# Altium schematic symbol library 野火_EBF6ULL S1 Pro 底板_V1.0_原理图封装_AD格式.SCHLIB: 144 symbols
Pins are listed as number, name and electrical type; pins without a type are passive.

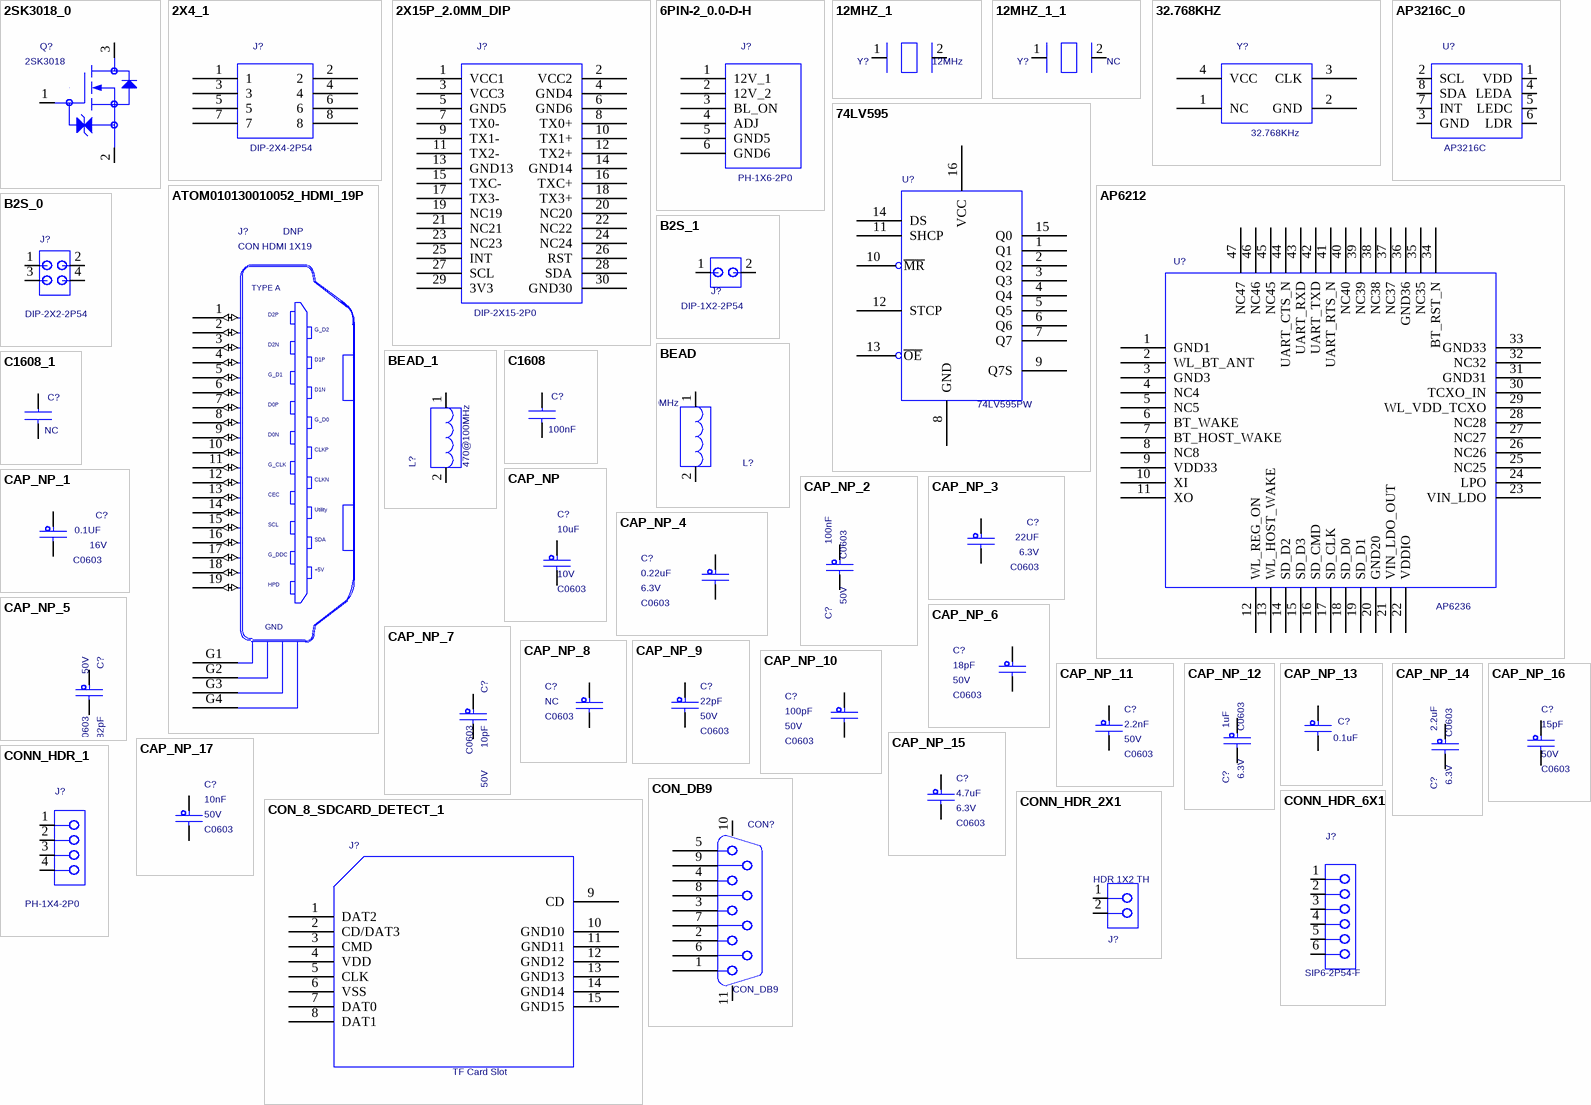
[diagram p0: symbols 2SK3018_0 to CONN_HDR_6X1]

## 2SK3018_0
designator Q?  value 2SK3018  (hidden comment: 2SK3018_0)
TRANS MOSFET N-CH 30V .1A SOT-323; PCB DECAL: SOT23; AGILE_PN: 480-75317; MFG_NAME01: ROHM; MFG_PN01: 2SK3018T106; CAD_APPROVED: Yes; Source_Path: H:\NXP_RT1050\SCH\CORE_SCH\IMXRT1052_180113.DSN; CLASS: IC
footprint SOT23
pins: 1 GATE, 2 SOURCE, 3 DRAIN

## 2X4_1
designator J?  value DIP-2X4-2P54  (hidden comment: 2X4_1)
Source_Path: D:\NXP_RT1050\RT1050_MB_PRO\SCH\IMXRT1052_MB_PRO_0321.DSN
footprint DIP-2X4-2P54
pins: 1, 2, 3, 4, 5, 6, 7, 8

## 2X15P_2.0MM_DIP
designator J?  value DIP-2X15-2P0  (hidden comment: 2X15P_2.0MM_DIP)
Source_Path: H:\NXP_RT1050\SCH\SCHLIB\YHSCHLIB.OLB
footprint DIP-2X15-2P0
pins: 1 VCC1, 2 VCC2, 3 VCC3, 4 GND4, 5 GND5, 6 GND6, 7 TX0-, 8 TX0+, 9 TX1-, 10 TX1+, 11 TX2-, 12 TX2+, 13 GND13, 14 GND14, 15 TXC-, 16 TXC+, 17 TX3-, 18 TX3+, 19 NC19, 20 NC20, 21 NC21, 22 NC22, 23 NC23, 24 NC24, 25 INT, 26 RST, 27 SCL, 28 SDA, 29 3V3, 30 GND30

## 6PIN-2_0.0-D-H
designator J?  value PH-1X6-2P0  (hidden comment: 6PIN-2_0.0-D-H)
Source_Path: H:\NXP_RT1050\SCH\IMXRT1052_MB.DSN
footprint PH-1X6-2P0
pins: 1 12V_1, 2 12V_2, 3 BL_ON, 4 ADJ, 5 GND5, 6 GND6

## 12MHZ_1
designator Y?  value 12MHz  (hidden comment: 12MHZ_1)
PCB DECAL: XTAL-DIP; Source_Path: H:\NXP_RT1050\SCH\IMXRT1052_MB.DSN
footprint XTAL-DIP
pins: 1, 2

## 12MHZ_1_1
designator Y?, comment value NC  (hidden comment: 12MHZ_1)
PCB DECAL: XTAL-DIP; Source_Path: H:\NXP_RT1050\SCH\IMXRT1052_MB.DSN
footprint XTAL-DIP
pins: 1, 2

## 32.768KHZ
designator Y?
PCB DECAL: 3225; Source_Path: F:\NXP\I.MX6UL\SCH\IMX6UL.OLB
footprint 3225
pins: 1 NC, 2 GND, 3 CLK, 4 VCC

## 74LV595
designator U?  value 74LV595PW  (hidden comment: 74LV595)
IC REG S 8BIT TS 1.0-3.6V TSSOP16; CAD_APPROVED: Yes; MFG_NAME01: PHILIPS SEMICONDUCTOR; AGILE_PN: 312-79843; Source_Path: Q:\ORCADCIS\SYMBOLS\FCL_IC5.OLB
footprint TSSOP16
pins: 1 Q1, 2 Q2, 3 Q3, 4 Q4, 5 Q5, 6 Q6, 7 Q7, 8 GND (power), 9 Q7S, 10 ~{MR}, 11 SHCP, 12 STCP, 13 ~{OE}, 14 DS, 15 Q0, 16 VCC (power)

## AP3216C_0
designator U?  value AP3216C  (hidden comment: AP3216C_0)
Source_Path: D:\NXP_RT1050\RT1050_MB_PRO\SCH\IMXRT1052_MB_PRO_0414.DSN
footprint AP3216C
pins: 1 VDD, 2 SCL, 3 GND, 4 LEDA, 5 LEDC, 6 LDR, 7 INT, 8 SDA

## AP6212
designator U?  value AP6236  (hidden comment: AP6212)
Source_Path: F:\NXP\I.MX6UL\SCH\IMX6UL.OLB
footprint AP6212
pins: 1 GND1, 2 WL_BT_ANT, 3 GND3, 4 NC4, 5 NC5, 6 BT_WAKE, 7 BT_HOST_WAKE, 8 NC8, 9 VDD33, 10 XI, 11 XO, 12 WL_REG_ON, 13 WL_HOST_WAKE, 14 SD_D2, 15 SD_D3, 16 SD_CMD, 17 SD_CLK, 18 SD_D0, 19 SD_D1, 20 GND20, 21 VIN_LDO_OUT, 22 VDDIO, 23 VIN_LDO, 24 LPO, 25 NC25, 26 NC26, 27 NC27, 28 NC28, 29 WL_VDD_TCXO, 30 TCXO_IN, 31 GND31, 32 NC32, 33 GND33, 34 BT_RST_N, 35 NC35, 36 GND36, 37 NC37, 38 NC38, 39 NC39, 40 NC40, 41 UART_RTS_N, 42 UART_TXD, 43 UART_RXD, 44 UART_CTS_N, 45 NC45, 46 NC46, 47 NC47

## ATOM010130010052_HDMI_19P
designator J?  value CON HDMI 1X19  ASSY_OPT: DNP  (hidden comment: ATOM010130010052_HDMI_19P)
CON 1X19 HDMI SMT 0.5MM 249H AU --; CAD_APPROVED: Yes; MFG_PN01: HD119F-3A04202; MFG_NAME01: SHENZHEN ATOM TECHNOLOGY CO.,LTD; AGILE_PN: 211-79674; PCB DECAL: CON_RA_HDMI_19P_0P5_SM; Source_Path: Q:\ORCADCIS\SYMBOLS\FCL_CONNECTOR.OLB; VPN: 1166-2C105-211; Vendor: Comtek; OriginalSymbolOrigin: (-200,650); CLASS: IO
footprint CON_RA_HDMI_19P_0P5_SM
pins: 1 D2+ (io), 2 D2GND (io), 3 D2- (io), 4 D1+ (io), 5 D1GND (io), 6 D1- (io), 7 D0+ (io), 8 D0GND (io), 9 D0- (io), 10 CK+ (io), 11 CKGND (io), 12 CK- (io), 13 CEC (io), 14 UTILITY (io), 15 SCL (io), 16 SDA (io), 17 DDCGND (io), 18 +5V (io), 19 HPD (io), G1 GND1 (power), G2 GND2 (power), G3 GND3 (power), G4 GND4 (power)

## B2S_0
designator J?  value DIP-2X2-2P54  (hidden comment: B2S_0)
Source_Path: E:\20200901_FPGA_A7\DEV\VERSION7\EBF_XC7A35T B1 DEV BOARD_20201024001.DSN
footprint DIP-2X2-2P54
pins: 1, 2, 3, 4

## B2S_1
designator J?  value DIP-1X2-2P54  (hidden comment: B2S_1)
PCB DECAL: HDR102; Source_Path: F:\STM32\F429\SCH\V4\STM32F429_F767_H743_MB_1129.DSN
footprint HDR102
pins: 1, 2

## BEAD
designator L?  value 330@100MHz  (hidden comment: BEAD)
IND FER BEAD 330OHM@100MHZ 1.7A 0603; PART_TYPE: FERRITE\BEAD; TOL: 25%; CAD_APPROVED: Yes; MFG_PN01: MPZ1608S331A; MFG_NAME01: TDK; AGILE_PN: 180-78156; PCB DECAL: L0603; Source_Path: Q:\ORCADCIS\SYMBOLS\FCL_INDUCTOR.OLB; CLASS: DISCRETE
footprint L0603
pins: 1, 2

## BEAD_1
designator L?, comment value 470@100MHz  (hidden comment: BEAD)
IND FER BEAD 330OHM@100MHZ 1.7A 0603; PART_TYPE: FERRITE\BEAD; PCB DECAL: L0603; AGILE_PN: 180-78156; Tolerance: 25%; MFG_NAME01: TDK; MFG_PN01: MPZ1608S331A; CAD_APPROVED: Yes; Source_Path: Q:\ORCADCIS\SYMBOLS\FCL_INDUCTOR.OLB; CLASS: DISCRETE
footprint L0603
pins: 1, 2

## C1608
designator C?  value 100nF  (hidden comment: C1608)
PCB DECAL: C0603; Source_Path: D:\SOPGODS_VIEW_AP\MOBILE_AP_APPLICATION\LIBRARY\ORCAD\DEVICE.OLB
footprint C0603
pins: 1, 2

## C1608_1
designator C?, comment value NC  (hidden comment: C1608)
PCB DECAL: C0603; Source_Path: D:\SOPGODS_VIEW_AP\MOBILE_AP_APPLICATION\LIBRARY\ORCAD\DEVICE.OLB
footprint C0603
pins: 1, 2

## CAP_NP
designator C?  value 10uF  PCB DECAL: C0603  voltage_rating: 10V  (hidden comment: CAP_NP)
CAP CER 22UF 6.3V 20% X5R 0603; FPLIST: CC0603_OV,CC0603,0603_CC; CAD_APPROVED: Yes; MFG_PN01: CL10A226MQ8NRNE; MFG_NAME01: Samsung; AGILE_PN: 150-78467; Source_Path: Q:\ORCADCIS\SYMBOLS\FCL_CAPACITOR.OLB; CLASS: DISCRETE
footprint C0603
pins: 1, 2

## CAP_NP_1
designator C?, comment value 0.1UF  voltage_rating: 16V  PCB DECAL: C0603  (hidden comment: CAP_NP)
CAP CER 22UF 6.3V 20% X5R 0603; AGILE_PN: 150-78467; MFG_NAME01: Samsung; MFG_PN01: CL10A226MQ8NRNE; CAD_APPROVED: Yes; FPLIST: CC0603_OV,CC0603,0603_CC; Source_Path: Q:\ORCADCIS\SYMBOLS\FCL_CAPACITOR.OLB; CLASS: DISCRETE
footprint C0603
pins: 1, 2

## CAP_NP_2
designator C?, comment value 100nF  voltage_rating: 50V  PCB DECAL: C0603  (hidden comment: CAP_NP)
CAP CER 22UF 6.3V 20% X5R 0603; FPLIST: CC0603_OV,CC0603,0603_CC; CAD_APPROVED: Yes; MFG_PN01: CL10A226MQ8NRNE; MFG_NAME01: Samsung; AGILE_PN: 150-78467; Source_Path: Q:\ORCADCIS\SYMBOLS\FCL_CAPACITOR.OLB; CLASS: DISCRETE
footprint C0603
pins: 1, 2

## CAP_NP_3
designator C?, comment value 22UF  PCB DECAL: C0603  voltage_rating: 6.3V  (hidden comment: CAP_NP)
CAP CER 22UF 6.3V 20% X5R 0603; AGILE_PN: 150-78467; MFG_NAME01: Samsung; MFG_PN01: CL10A226MQ8NRNE; CAD_APPROVED: Yes; FPLIST: CC0603_OV,CC0603,0603_CC; Source_Path: Q:\ORCADCIS\SYMBOLS\FCL_CAPACITOR.OLB; CLASS: DISCRETE
footprint C0603
pins: 1, 2

## CAP_NP_4
designator C?, comment value 0.22uF  PCB DECAL: C0603  VOLTAGE: 6.3V  (hidden comment: CAP_NP)
CAP CER 0.22UF 6.3V 20% X5R 0402; AGILE_PN: 150-76271; MFG_NAME01: KEMET; MFG_PN01: C0402C224M9PAC; CAD_APPROVED: Yes; FPLIST: CC0402_25,CC0402_HD,0402_CC; Source_Path: Q:\ORCADCIS\SYMBOLS\FCL_CAPACITOR.OLB; CLASS: DISCRETE
footprint C0603
pins: 1, 2

## CAP_NP_5
designator C?, comment value 82pF  voltage_rating: 50V  PCB DECAL: C0603  (hidden comment: CAP_NP)
CAP CER 22UF 6.3V 20% X5R 0603; FPLIST: CC0603_OV,CC0603,0603_CC; CAD_APPROVED: Yes; MFG_PN01: CL10A226MQ8NRNE; MFG_NAME01: Samsung; AGILE_PN: 150-78467; Source_Path: Q:\ORCADCIS\SYMBOLS\FCL_CAPACITOR.OLB; CLASS: DISCRETE
footprint C0603
pins: 1, 2

## CAP_NP_6
designator C?, comment value 18pF  voltage_rating: 50V  PCB DECAL: C0603  (hidden comment: CAP_NP)
CAP CER 22UF 6.3V 20% X5R 0603; FPLIST: CC0603_OV,CC0603,0603_CC; CAD_APPROVED: Yes; MFG_PN01: CL10A226MQ8NRNE; MFG_NAME01: Samsung; AGILE_PN: 150-78467; Source_Path: Q:\ORCADCIS\SYMBOLS\FCL_CAPACITOR.OLB; CLASS: DISCRETE
footprint C0603
pins: 1, 2

## CAP_NP_7
designator C?, comment value 10pF  voltage_rating: 50V  PCB DECAL: C0603  (hidden comment: CAP_NP)
CAP CER 22UF 6.3V 20% X5R 0603; FPLIST: CC0603_OV,CC0603,0603_CC; CAD_APPROVED: Yes; MFG_PN01: CL10A226MQ8NRNE; MFG_NAME01: Samsung; AGILE_PN: 150-78467; Source_Path: Q:\ORCADCIS\SYMBOLS\FCL_CAPACITOR.OLB; CLASS: DISCRETE
footprint C0603
pins: 1, 2

## CAP_NP_8
designator C?, comment value NC  PCB DECAL: C0603  (hidden comment: CAP_NP)
CAP CER 22UF 6.3V 20% X5R 0603; voltage_rating: 50V; AGILE_PN: 150-78467; MFG_NAME01: Samsung; MFG_PN01: CL10A226MQ8NRNE; CAD_APPROVED: Yes; FPLIST: CC0603_OV,CC0603,0603_CC; Source_Path: Q:\ORCADCIS\SYMBOLS\FCL_CAPACITOR.OLB; CLASS: DISCRETE
footprint C0603
pins: 1, 2

## CAP_NP_9
designator C?, comment value 22pF  PCB DECAL: C0603  voltage_rating: 50V  (hidden comment: CAP_NP)
CAP CER 22UF 6.3V 20% X5R 0603; AGILE_PN: 150-78467; MFG_NAME01: Samsung; MFG_PN01: CL10A226MQ8NRNE; CAD_APPROVED: Yes; FPLIST: CC0603_OV,CC0603,0603_CC; Source_Path: Q:\ORCADCIS\SYMBOLS\FCL_CAPACITOR.OLB; CLASS: DISCRETE
footprint C0603
pins: 1, 2

## CAP_NP_10
designator C?, comment value 100pF  PCB DECAL: C0603  voltage_rating: 50V  (hidden comment: CAP_NP)
CAP CER 22UF 6.3V 20% X5R 0603; FPLIST: CC0603_OV,CC0603,0603_CC; CAD_APPROVED: Yes; MFG_PN01: CL10A226MQ8NRNE; MFG_NAME01: Samsung; AGILE_PN: 150-78467; Source_Path: Q:\ORCADCIS\SYMBOLS\FCL_CAPACITOR.OLB; CLASS: DISCRETE
footprint C0603
pins: 1, 2

## CAP_NP_11
designator C?, comment value 2.2nF  voltage_rating: 50V  PCB DECAL: C0603  (hidden comment: CAP_NP)
CAP CER 22UF 6.3V 20% X5R 0603; FPLIST: CC0603_OV,CC0603,0603_CC; CAD_APPROVED: Yes; MFG_PN01: CL10A226MQ8NRNE; MFG_NAME01: Samsung; AGILE_PN: 150-78467; Source_Path: Q:\ORCADCIS\SYMBOLS\FCL_CAPACITOR.OLB; CLASS: DISCRETE
footprint C0603
pins: 1, 2

## CAP_NP_12
designator C?, comment value 1uF  voltage_rating: 6.3V  PCB DECAL: C0603  (hidden comment: CAP_NP)
CAP CER 22UF 6.3V 20% X5R 0603; FPLIST: CC0603_OV,CC0603,0603_CC; CAD_APPROVED: Yes; MFG_PN01: CL10A226MQ8NRNE; MFG_NAME01: Samsung; AGILE_PN: 150-78467; Source_Path: Q:\ORCADCIS\SYMBOLS\FCL_CAPACITOR.OLB; CLASS: DISCRETE
footprint C0603
pins: 1, 2

## CAP_NP_13
designator C?, comment value 0.1uF  (hidden comment: CAP_NP)
CAP CER 0.1UF 10V 10% X5R 0402; PCB DECAL: C0603; FPLIST: CC0402_25,CC0402_HD,0402_CC; CAD_APPROVED: Yes; MFG_PN01: C0402C104K8PAC; MFG_NAME01: KEMET; AGILE_PN: 150-75634; Source_Path: Q:\ORCADCIS\SYMBOLS\FCL_CAPACITOR.OLB; CLASS: DISCRETE
footprint C0603
pins: 1, 2

## CAP_NP_14
designator C?, comment value 2.2uF  voltage_rating: 6.3V  PCB DECAL: C0603  (hidden comment: CAP_NP)
CAP CER 22UF 6.3V 20% X5R 0603; AGILE_PN: 150-78467; MFG_NAME01: Samsung; MFG_PN01: CL10A226MQ8NRNE; CAD_APPROVED: Yes; FPLIST: CC0603_OV,CC0603,0603_CC; Source_Path: Q:\ORCADCIS\SYMBOLS\FCL_CAPACITOR.OLB; CLASS: DISCRETE
footprint C0603
pins: 1, 2

## CAP_NP_15
designator C?, comment value 4.7uF  PCB DECAL: C0603  voltage_rating: 6.3V  (hidden comment: CAP_NP)
CAP CER 22UF 6.3V 20% X5R 0603; AGILE_PN: 150-78467; MFG_NAME01: Samsung; MFG_PN01: CL10A226MQ8NRNE; CAD_APPROVED: Yes; FPLIST: CC0603_OV,CC0603,0603_CC; Source_Path: Q:\ORCADCIS\SYMBOLS\FCL_CAPACITOR.OLB; CLASS: DISCRETE
footprint C0603
pins: 1, 2

## CAP_NP_16
designator C?, comment value 15pF  PCB DECAL: C0603  voltage_rating: 50V  (hidden comment: CAP_NP)
CAP CER 22UF 6.3V 20% X5R 0603; AGILE_PN: 150-78467; MFG_NAME01: Samsung; MFG_PN01: CL10A226MQ8NRNE; CAD_APPROVED: Yes; FPLIST: CC0603_OV,CC0603,0603_CC; Source_Path: Q:\ORCADCIS\SYMBOLS\FCL_CAPACITOR.OLB; CLASS: DISCRETE
footprint C0603
pins: 1, 2

## CAP_NP_17
designator C?, comment value 10nF  PCB DECAL: C0603  voltage_rating: 50V  (hidden comment: CAP_NP)
CAP CER 22UF 6.3V 20% X5R 0603; FPLIST: CC0603_OV,CC0603,0603_CC; CAD_APPROVED: Yes; MFG_PN01: CL10A226MQ8NRNE; MFG_NAME01: Samsung; AGILE_PN: 150-78467; Source_Path: Q:\ORCADCIS\SYMBOLS\FCL_CAPACITOR.OLB; CLASS: DISCRETE
footprint C0603
pins: 1, 2

## CON_8_SDCARD_DETECT_1
designator J?  value TF Card Slot  (hidden comment: CON_8_SDCARD_DETECT_1)
CON 8 SKT SD/MMC PUSH-PUSH RA SMT 1.1MM SP 83H AU; PCB DECAL: TFCARD; AGILE_PN: 211-80105; MFG_NAME01: ANYTRONIC CORPORATION LIMITED; MFG_PN01: 95060030-14RRF; CAD_APPROVED: Yes; Source_Path: H:\NXP_RT1050\SCH\IMXRT1052_MB.DSN; CLASS: IO
footprint TFCARD
pins: 1 DAT2, 2 CD/DAT3, 3 CMD, 4 VDD (power), 5 CLK, 6 VSS (power), 7 DAT0, 8 DAT1, 9 CD, 10 GND10, 11 GND11, 12 GND12, 13 GND13, 14 GND14, 15 GND15

## CON_DB9
designator CON?
PCB DECAL: DB9-M; Source_Path: E:\WORK\LIB\ORCAD_SCH\MYLIB_10120926.OLB
footprint DB9-M
pins: 1, 2, 3, 4, 5, 6, 7, 8, 9, 10, 11

## CONN_HDR_1
designator J?  value PH-1X4-2P0  (hidden comment: CONN_HDR_1)
HDR 1X2 TH 100MIL SP 339H AU 98L; AGILE_PN: 210-75439; MFG_NAME01: SAMTEC; MFG_PN01: TSW-102-07-G-S; ASSY_OPT: DNP; CAD_APPROVED: YES; Source_Path: D:\NXP_RT1050\RT1050_MB_PRO\SCH\IMXRT1052_MB_PRO_0417_3.DSN; CLASS: IO
footprint PH-1X4-2P0
pins: 1, 2, 3, 4

## CONN_HDR_2X1
designator J?  value HDR 1X2 TH  (hidden comment: CONN_HDR_2X1)
HDR 1X2 TH 100MIL SP 339H AU 98L; PCB DECAL: CON_2PIN; AGILE_PN: 210-75439; MFG_NAME01: SAMTEC; MFG_PN01: TSW-102-07-G-S; CAD_APPROVED: YES; Source_Path: Q:\ORCADCIS\SYMBOLS\FCL_CONNECTOR.OLB; CLASS: IO
footprint CON_2PIN
pins: 1, 2

## CONN_HDR_6X1
designator J?  value SIP6-2P54-F  (hidden comment: CONN_HDR_6X1)
CON 1X6 SKT TH 100MIL SP 344H AU 118L; CAD_APPROVED: Yes; ASSY_OPT: DNP; Temp_Range: -40°C to +105°C; MFG_PN01: 08001S3 0611-29RF; MFG_NAME01: ANYTRONIC CORPORATION LIMITED; AGILE_PN: 210-81616; PCB DECAL: SIP6-2P54; Source_Path: Q:\ORCADCIS\SYMBOLS\FCL_CONNECTOR.OLB; CLASS: IO
footprint SIP6-2P54
pins: 1, 2, 3, 4, 5, 6

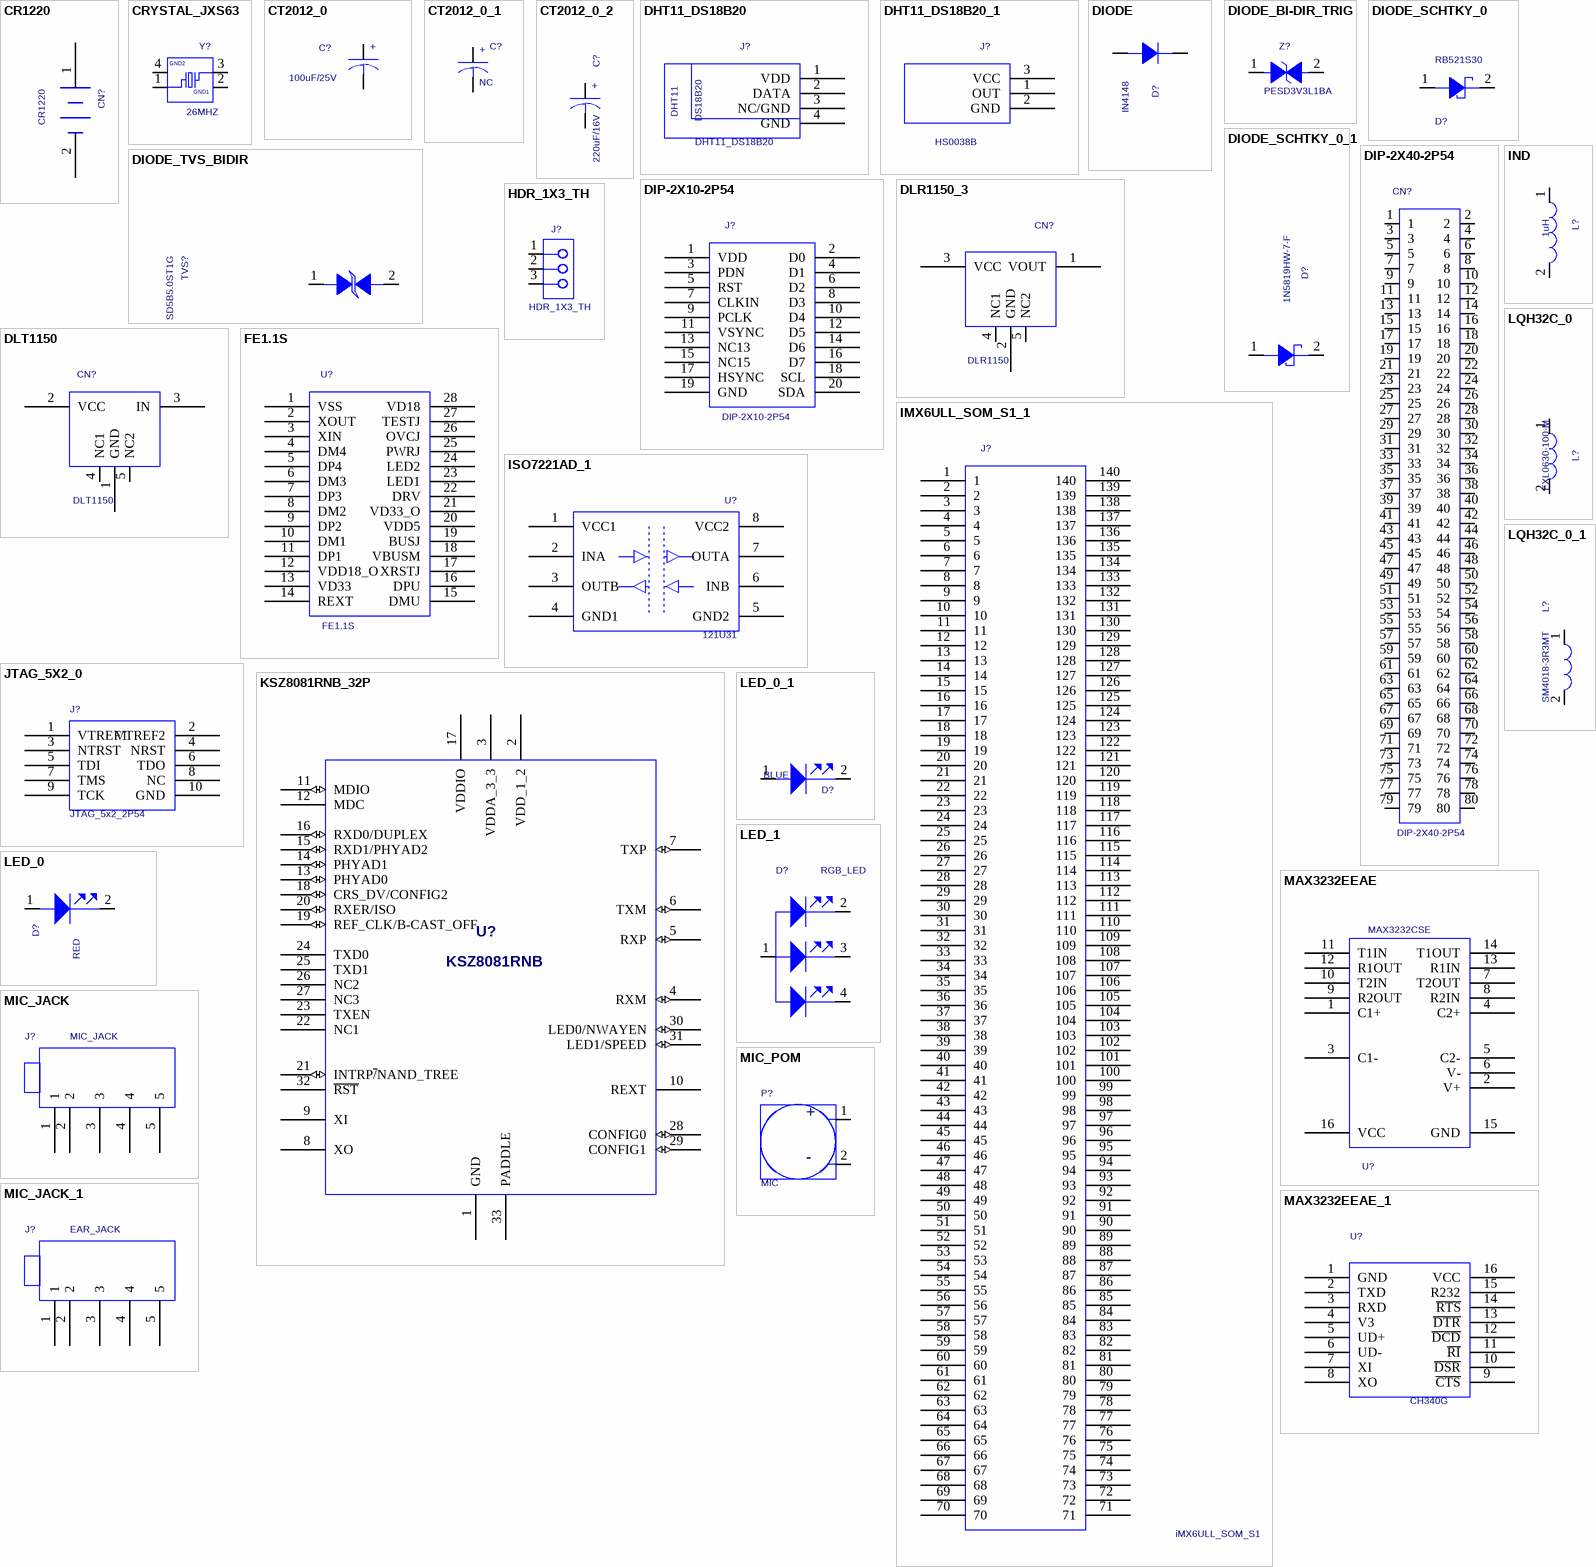
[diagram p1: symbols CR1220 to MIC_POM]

## CR1220
designator CN?
Source_Path: H:\NXP_RT1050\SCH\SCHLIB\YHSCHLIB.OLB
footprint CR1220
pins: 1 BAT, 2 GND

## CRYSTAL_JXS63
designator Y?  value 26MHZ  (hidden comment: CRYSTAL_JXS63)
XTAL 24MHZ -- 30PPM 3.2X2.5MM SMD; PCB DECAL: 3225; AGILE_PN: 230-77452; MFG_NAME01: TXC CORP; MFG_PN01: 7V24000002; CAD_APPROVED: Yes; Source_Path: Q:\ORCADCIS\SYMBOLS\FCL_XTAL_OSC.OLB; CLASS: IC
footprint 3225
pins: 1, 2 GND1 (power), 3, 4 GND2 (power)

## CT2012_0
designator C?  value 100uF/25V  (hidden comment: CT2012_0)
PCB DECAL: EC6P3; Source_Path: D:\01_LSI_PROJECT\C100\00.SMDK俺惯\SCHEMATICS\C100\C100_CPU.OLB
footprint EC6P3
pins: 1, 2

## CT2012_0_1
designator C?, comment value NC  (hidden comment: CT2012_0)
PCB DECAL: CAP100; Source_Path: D:\01_LSI_PROJECT\C100\00.SMDK俺惯\SCHEMATICS\C100\C100_CPU.OLB
footprint CAP100
pins: 1, 2

## CT2012_0_2
designator C?, comment value 220uF/16V  (hidden comment: CT2012_0)
PCB DECAL: EC6P3; Source_Path: D:\01_LSI_PROJECT\C100\00.SMDK俺惯\SCHEMATICS\C100\C100_CPU.OLB
footprint EC6P3
pins: 1, 2

## DHT11_DS18B20
designator J?
PCB DECAL: SIP4-2P54; Source_Path: H:\NXP_RT1050\SCH\SCHLIB\YHSCHLIB.OLB
footprint SIP4-2P54
pins: 1 VDD, 2 DATA, 3 NC/GND, 4 GND

## DHT11_DS18B20_1
designator J?  value HS0038B  (hidden comment: DHT11_DS18B20_1)
PCB DECAL: SIP3-2P54; Source_Path: D:\NXP_RT1050\RT1050_MB_PRO\SCH\IMXRT1052_MB_PRO_0413.DSN
footprint SIP3-2P54
pins: 1 OUT, 2 GND, 3 VCC

## DIODE
designator D?  value IN4148  (hidden comment: DIODE)
PCB DECAL: SOD-123; Source_Path: C:\CADENCE\SPB_16.2\TOOLS\CAPTURE\LIBRARY\DISCRETE.OLB
footprint SOD-123
pins: 1 A, 2 K

## DIODE_BI-DIR_TRIG
designator Z?  value PESD3V3L1BA  (hidden comment: DIODE_BI-DIR_TRIG)
PCB DECAL: SOD323; ROOM: B-VGA_IN; Assembly: NC; Source_Path: D:\PCB_DATA\ORCAD_LIB\LRY2.OLB
footprint SOD323
pins: 1, 2

## DIODE_SCHTKY_0
designator D?  value RB521S30  (hidden comment: DIODE_SCHTKY_0)
DIODE SCH RECT 200MA 30V AEC-Q101 SOD-523; PCB DECAL: SOD523; CAD_APPROVED: Yes; MFG_PN01: RB521S30,115; MFG_NAME01: NEXPERIA; AGILE_PN: 480-79672; Source_Path: H:\NXP_RT1050\SCH\IMXRT1052_CORE\CORE\IMXRT1052_1207.DSN; CLASS: IC
footprint SOD523
pins: 1, 2

## DIODE_SCHTKY_0_1
designator D?, comment value 1N5819HW-7-F  (hidden comment: DIODE_SCHTKY_0)
DIODE SCH RECT 200MA 30V AEC-Q101 SOD-523; PCB DECAL: SOD123; AGILE_PN: 480-79672; MFG_NAME01: NEXPERIA; MFG_PN01: RB521S30,115; CAD_APPROVED: Yes; Source_Path: H:\NXP_RT1050\SCH\IMXRT1052_CORE\CORE\IMXRT1052_1207.DSN; CLASS: IC
footprint SOD123
pins: 1, 2

## DIODE_TVS_BIDIR
designator TVS?  value ESD5B5.0ST1G  (hidden comment: DIODE_TVS_BIDIR)
DIODE SUPPRESSOR 16A@30NS 5V@1UA SOD-523; PCB DECAL: SOD523; CAD_APPROVED: Yes; ASSY_OPT: DNP; MFG_NAME01: on semiconductor; AGILE_PN: 480-76937; Source_Path: Q:\ORCADCIS\SYMBOLS\FCL_SEMICONDUCTOR.OLB; CLASS: IC
footprint SOD523
pins: 1 A1, 2 A2

## DIP-2X10-2P54
designator J?
Source_Path: H:\NXP_RT1050\SCH\SCHLIB\YHSCHLIB.OLB
footprint DIP-2X10-2P54
pins: 1 VDD, 2 D0, 3 PDN, 4 D1, 5 RST, 6 D2, 7 CLKIN, 8 D3, 9 PCLK, 10 D4, 11 VSYNC, 12 D5, 13 NC13, 14 D6, 15 NC15, 16 D7, 17 HSYNC, 18 SCL, 19 GND, 20 SDA

## DIP-2X40-2P54
designator CN?
Source_Path: F:\NXP\I.MX6UL\SCH\IMX6UL.OLB
footprint DIP-2X40-2P54
pins: 1, 2, 3, 4, 5, 6, 7, 8, 9, 10, 11, 12, 13, 14, 15, 16, 17, 18, 19, 20, 21, 22, 23, 24, 25, 26, 27, 28, 29, 30, 31, 32, 33, 34, 35, 36, 37, 38, 39, 40, 41, 42, 43, 44, 45, 46, 47, 48, 49, 50, 51, 52, 53, 54, 55, 56, 57, 58, 59, 60, 61, 62, 63, 64, 65, 66, 67, 68, 69, 70, 71, 72, 73, 74, 75, 76, 77, 78, 79, 80

## DLR1150_3
designator CN?  value DLR1150  (hidden comment: DLR1150_3)
Source_Path: F:\STM32\H750\SCH\野火_H750 PRO底板_原理图_V1_0.DSN
footprint DLR1150
pins: 1 VOUT, 2 GND, 3 VCC, 4 NC1, 5 NC2

## DLT1150
designator CN?
Source_Path: F:\NXP\I.MX6UL\SCH\IMX6UL.OLB
footprint DLT1150
pins: 1 GND, 2 VCC, 3 IN, 4 NC1, 5 NC2

## FE1.1S
designator U?
PCB DECAL: SSOP-28; Source_Path: G:\开发板代码\郭老师资料\IMX6资料\原理图\SABRESDB_DESIGNFILES\DEVELOP\LIBRARY1.OLB
footprint SSOP-28
pins: 1 VSS, 2 XOUT, 3 XIN, 4 DM4, 5 DP4, 6 DM3, 7 DP3, 8 DM2, 9 DP2, 10 DM1, 11 DP1, 12 VDD18_O, 13 VD33, 14 REXT, 15 DMU, 16 DPU, 17 XRSTJ, 18 VBUSM, 19 BUSJ, 20 VDD5, 21 VD33_O, 22 DRV, 23 LED1, 24 LED2, 25 PWRJ, 26 OVCJ, 27 TESTJ, 28 VD18

## HDR_1X3_TH
designator J?
Source_Path: D:\NXP_RT1050\RT1050_MB_PRO\SCH\LIBRARY1.OLB; CLASS: IO
footprint HDR_1X3_TH
pins: 1, 2, 3

## IMX6ULL_SOM_S1_1
designator J?  value iMX6ULL_SOM_S1  (hidden comment: IMX6ULL_SOM_S1_1)
PCB DECAL: IMX6ULL_SOM_S1_140P_39X39; Source_Path: F:\SCH-PCB\EBF_L004\SCH\EBF_L004_0620.DSN
footprint IMX6ULL_SOM_S1_140P_39X39
pins: 1, 2, 3, 4, 5, 6, 7, 8, 9, 10, 11, 12, 13, 14, 15, 16, 17, 18, 19, 20, 21, 22, 23, 24, 25, 26, 27, 28, 29, 30, 31, 32, 33, 34, 35, 36, 37, 38, 39, 40, 41, 42, 43, 44, 45, 46, 47, 48, 49, 50, 51, 52, 53, 54, 55, 56, 57, 58, 59, 60, 61, 62, 63, 64, 65, 66, 67, 68, 69, 70, 71, 72, 73, 74, 75, 76, 77, 78, 79, 80, 81, 82, 83, 84, 85, 86, 87, 88, 89, 90, 91, 92, 93, 94, 95, 96, 97, 98, 99, 100, 101, 102, 103, 104, 105, 106, 107, 108, 109, 110, 111, 112, 113, 114, 115, 116, 117, 118, 119, 120, 121, 122, 123, 124, 125, 126, 127, 128, 129, 130, 131, 132, 133, 134, 135, 136, 137, 138, 139, 140

## IND
designator L?  value 1uH  (hidden comment: IND)
IND PWR 1UH@100KHZ 2.6A 30% SMT; PART_TYPE: INDUCTOR\POWER; PCB DECAL: L4018; AGILE_PN: 180-77797; MFG_NAME01: Shenzhen Sunlord Electronics Co., Ltd; MFG_PN01: SWPA4020S1R0NT; CAD_APPROVED: Yes; Source_Path: Q:\ORCADCIS\SYMBOLS\FCL_INDUCTOR.OLB; CLASS: DISCRETE
footprint L4018
pins: 1, 2

## ISO7221AD_1
designator U?  value 121U31  (hidden comment: ISO7221AD_1)
Dual Digital Isolators, Opposite directions, 1 Mbps, -40℃ to +125℃; Mfr: TI; Mfr_Part_Number: ISO7221ADR; Part_Number: IC100205-01; Partname: 贴片IC; Gtech_Number: 60101IS7221ADR001; Remarks: Checked; Spec: ISO7221ADR SOIC8(TI); PCB DECAL: SOIC_8; Source_Path: E:\20200507_CH340串口模块\VERSION4\EBF_USB TO SERIAL PORT_20201207.DSN
footprint SOIC_8
pins: 1 VCC1 (power), 2 INA, 3 OUTB, 4 GND1 (power), 5 GND2 (power), 6 INB, 7 OUTA, 8 VCC2 (power)

## JTAG_5X2_0
designator J?  value JTAG_5x2_2P54  (hidden comment: JTAG_5X2_0)
Source_Path: F:\SCH-PCB\EBF_L002\SCH\EBF_L002.DSN
footprint JTAG_5X2_2P54
pins: 1 VTREF1, 2 VTREF2, 3 NTRST, 4 NRST, 5 TDI, 6 TDO, 7 TMS, 8 NC, 9 TCK, 10 GND

## KSZ8081RNB_32P
designator U?  value KSZ8081RNB  (hidden comment: KSZ8081RNB_32P)
IC XCVR 10/100M EPHY 3.3V QFN32; CAD_APPROVED: Yes; MFG_PN01: KSZ8081RNBIA; MFG_NAME01: Micrel; AGILE_PN: 312-81089; PCB DECAL: QFN32_0P5_EP3P3; Source_Path: Q:\ORCADCIS\SYMBOLS\FCL_IC5.OLB
footprint QFN32_0P5_EP3P3
pins: 1 GND (power), 2 VDD_1_2 (power), 3 VDDA_3_3 (power), 4 RXM (io), 5 RXP (io), 6 TXM (io), 7 TXP (io), 8 XO, 9 XI, 10 REXT, 11 MDIO (io), 12 MDC, 13 PHYAD0 (io), 14 PHYAD1 (io), 15 RXD1/PHYAD2 (io), 16 RXD0/DUPLEX (io), 17 VDDIO (power), 18 CRS_DV/CONFIG2 (io), 19 REF_CLK/B-CAST_OFF (io), 20 RXER/ISO (io), 21 INTRP~{/}NAND_TREE (io), 22 NC1, 23 TXEN, 24 TXD0, 25 TXD1, 26 NC2, 27 NC3, 28 CONFIG0 (io), 29 CONFIG1 (io), 30 LED0/NWAYEN (io), 31 LED1/SPEED (io), 32 ~{RST}, 33 PADDLE (power)

## LED_0
designator D?  value RED  (hidden comment: LED_0)
LED GRN SGL 25MA 0603; PCB DECAL: LED0603; CAD_APPROVED: Yes; MFG_PN01: KPT-1608SGC; MFG_NAME01: KINGBRIGHT; AGILE_PN: 370-76549; Source_Path: H:\NXP_RT1050\SCH\IMXRT1052_CORE\CORE\IMXRT1052_1207.DSN; CLASS: IC
footprint LED0603
pins: 1 ANODE, 2 CATHODE

## LED_0_1
designator D?, comment value BLUE  (hidden comment: LED_0)
LED GRN SGL 25MA 0603; PCB DECAL: LED0603; CAD_APPROVED: Yes; MFG_PN01: KPT-1608SGC; MFG_NAME01: KINGBRIGHT; AGILE_PN: 370-76549; Source_Path: H:\NXP_RT1050\SCH\IMXRT1052_CORE\CORE\IMXRT1052_1207.DSN; CLASS: IC
footprint LED0603
pins: 1 ANODE, 2 CATHODE

## LED_1
designator D?  value RGB_LED  (hidden comment: LED_1)
LED GRN SGL 25MA 0603; PCB DECAL: LED_RGB_5MM; CAD_APPROVED: Yes; MFG_PN01: KPT-1608SGC; MFG_NAME01: KINGBRIGHT; AGILE_PN: 370-76549; Source_Path: F:\STM32\H750\SCH\野火_H750 PRO底板_原理图_V1_0.DSN; CLASS: IC
footprint LED_RGB_5MM
pins: 1 ANODE, 2 R, 3 G, 4 B

## LQH32C_0
designator L?  value FXL0630-100-M  (hidden comment: LQH32C_0)
PCB DECAL: L0630; Source_Path: D:\USER\ALLEGRO\2009\APR\SMDK_S5PC110_BASE\CAPTURE\S5PC110_SMDK_BASE_BD_SCHEMATIC_REV0.0.DSN
footprint L0630
pins: 1, 2

## LQH32C_0_1
designator L?, comment value SM4018-3R3MT  (hidden comment: LQH32C_0)
PCB DECAL: L4018; Source_Path: D:\USER\ALLEGRO\2009\APR\SMDK_S5PC110_BASE\CAPTURE\S5PC110_SMDK_BASE_BD_SCHEMATIC_REV0.0.DSN
footprint L4018
pins: 1, 2

## MAX3232EEAE
designator U?  value MAX3232CSE  (hidden comment: MAX3232EEAE)
PCB DECAL: SOIC16; Source_Path: E:\WORKS\PCB_DESIGN\CADENCE\LIB\PACKAGE_LIB\PACKAGE.OLB
footprint SOIC16
pins: 1 C1+, 2 V+, 3 C1-, 4 C2+, 5 C2-, 6 V-, 7 T2OUT, 8 R2IN, 9 R2OUT, 10 T2IN, 11 T1IN, 12 R1OUT, 13 R1IN, 14 T1OUT, 15 GND (power), 16 VCC (power)

## MAX3232EEAE_1
designator U?  value CH340G  (hidden comment: MAX3232EEAE_1)
PCB DECAL: SOIC16; Source_Path: H:\NXP_RT1050\SCH\IMXRT1052_MB.DSN
footprint SOIC16
pins: 1 GND, 2 TXD, 3 RXD, 4 V3, 5 UD+, 6 UD-, 7 XI, 8 XO, 9 ~{CTS}, 10 ~{DSR}, 11 ~{RI}, 12 ~{DCD}, 13 ~{DTR}, 14 ~{RTS}, 15 R232, 16 VCC (power)

## MIC_JACK
designator J?
PCB DECAL: EAR_JACK; Source_Path: H:\NXP_RT1050\SCH\SCHLIB\YHSCHLIB.OLB
footprint EAR_JACK
pins: 1, 2, 3, 4, 5

## MIC_JACK_1
designator J?, comment value EAR_JACK  (hidden comment: MIC_JACK)
Source_Path: H:\NXP_RT1050\SCH\SCHLIB\YHSCHLIB.OLB
footprint EAR_JACK
pins: 1, 2, 3, 4, 5

## MIC_POM
designator P?  value MIC  (hidden comment: MIC_POM)
AUDIO DEVICE MIC 0.5MA 2V 38-48+/-3dB 2.2KOHM 6MM TH; AGILE_PN: 510-77987; MFG_NAME01: Soberton Inc; MFG_PN01: EM6022P; CAD_APPROVED: Yes; PCB DECAL: MIC_6X2_2; Source_Path: Q:\ORCADCIS\SYMBOLS\FCL_MISC.OLB; CLASS: IC
footprint MIC_6X2_2
pins: 1 OUT, 2 GND

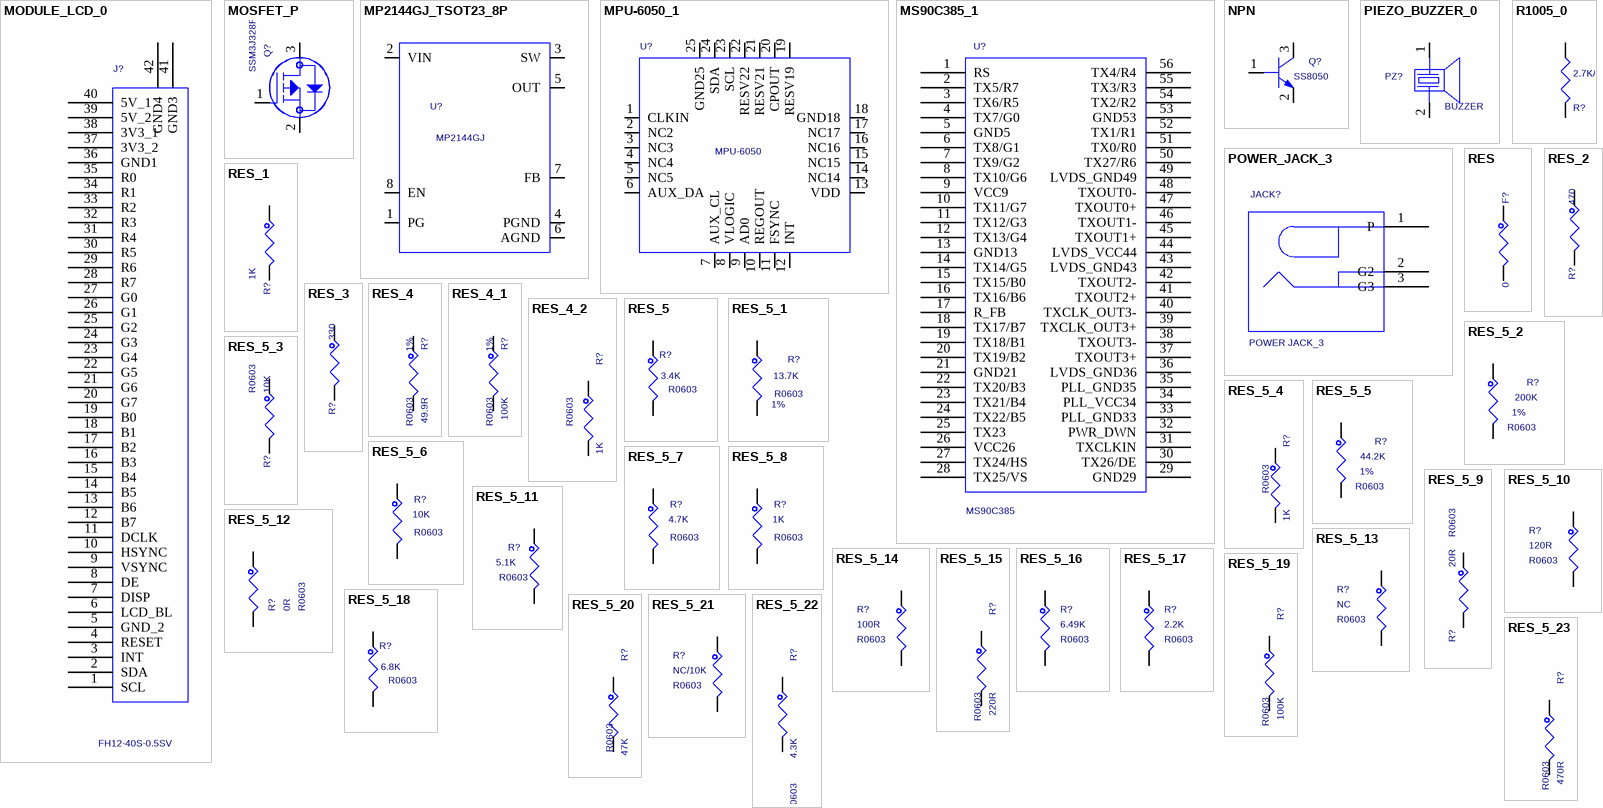
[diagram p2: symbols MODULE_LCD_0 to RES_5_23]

## MODULE_LCD_0
designator J?  value FH12-40S-0.5SV  (hidden comment: MODULE_LCD_0)
SUBASSEMBLY CON 1X40 FPC SMT RA + CON 1X6 FPC/FFC RA SKT + TFT DISPLAY 4.3INCH; PCB DECAL: FPC-40S-0P5SV; AGILE_PN: 750-77763; MFG_PN01: 211-79974,211-79976,375-00010; CAD_APPROVED: Yes; Source_Path: F:\SCH-PCB\EBF_L002\SCH\EBF_L002_0618.DSN; CLASS: IO
footprint FPC-40S-0P5SV
pins: 1 SCL, 2 SDA, 3 INT, 4 RESET, 5 GND_2, 6 LCD_BL, 7 DISP, 8 DE, 9 VSYNC, 10 HSYNC, 11 DCLK, 12 B7, 13 B6, 14 B5, 15 B4, 16 B3, 17 B2, 18 B1, 19 B0, 20 G7, 21 G6, 22 G5, 23 G4, 24 G3, 25 G2, 26 G1, 27 G0, 28 R7, 29 R6, 30 R5, 31 R4, 32 R3, 33 R2, 34 R1, 35 R0, 36 GND1, 37 3V3_2, 38 3V3_1, 39 5V_2, 40 5V_1, 41 GND3, 42 GND4

## MOSFET_P
designator Q?  value SSM3J328R  (hidden comment: MOSFET_P)
TRAN PMOS PWR 12V 4.3A SOT23; CAD_APPROVED: Yes; MFG_PN01: IRLML6401TRPBF; MFG_NAME01: INTERNATIONAL RECTIFIER; AGILE_PN: 480-77718; Source_Path: Q:\ORCADCIS\SYMBOLS\FCL_SEMICONDUCTOR.OLB; CLASS: IC
footprint SOT23
pins: 1 GATE, 2 SOURCE, 3 DRAIN

## MP2144GJ_TSOT23_8P
designator U?  value MP2144GJ  (hidden comment: MP2144GJ_TSOT23_8P)
IC SYNC STEP-DOWN SW 1.2MHZ 0.6V 2A 2.5-5.5V TSOT23-8; CAD_APPROVED: Yes; MFG_NAME01: MONOLITHIC POWER SYSTEMS; AGILE_PN: 315-80508; Source_Path: Q:\ORCADCIS\SYMBOLS\FCL_IC2.OLB
footprint TSOT23-8
pins: 1 PG (oc), 2 VIN (power), 3 SW, 4 PGND (power), 5 OUT, 6 AGND (power), 7 FB, 8 EN

## MPU-6050_1
designator U?  value MPU-6050  (hidden comment: MPU-6050_1)
PCB DECAL: QFN24; Source_Path: H:\NXP_RT1050\SCH\IMXRT1052_MB.DSN
footprint QFN24
pins: 1 CLKIN, 2 NC2, 3 NC3, 4 NC4, 5 NC5, 6 AUX_DA, 7 AUX_CL, 8 VLOGIC, 9 AD0, 10 REGOUT, 11 FSYNC, 12 INT, 13 VDD, 14 NC14, 15 NC15, 16 NC16, 17 NC17, 18 GND18, 19 RESV19, 20 CPOUT, 21 RESV21, 22 RESV22, 23 SCL, 24 SDA, 25 GND25

## MS90C385_1
designator U?  value MS90C385  (hidden comment: MS90C385_1)
PCB DECAL: TSSOP56; Source_Path: F:\STM32\F429\SCH\V4\STM32F429_F767_H743_MB.DSN
footprint TSSOP56
pins: 1 RS, 2 TX5/R7, 3 TX6/R5, 4 TX7/G0, 5 GND5, 6 TX8/G1, 7 TX9/G2, 8 TX10/G6, 9 VCC9, 10 TX11/G7, 11 TX12/G3, 12 TX13/G4, 13 GND13, 14 TX14/G5, 15 TX15/B0, 16 TX16/B6, 17 R_FB, 18 TX17/B7, 19 TX18/B1, 20 TX19/B2, 21 GND21, 22 TX20/B3, 23 TX21/B4, 24 TX22/B5, 25 TX23, 26 VCC26, 27 TX24/HS, 28 TX25/VS, 29 GND29, 30 TX26/DE, 31 TXCLKIN, 32 PWR_DWN, 33 PLL_GND33, 34 PLL_VCC34, 35 PLL_GND35, 36 LVDS_GND36, 37 TXOUT3+, 38 TXOUT3-, 39 TXCLK_OUT3+, 40 TXCLK_OUT3-, 41 TXOUT2+, 42 TXOUT2-, 43 LVDS_GND43, 44 LVDS_VCC44, 45 TXOUT1+, 46 TXOUT1-, 47 TXOUT0+, 48 TXOUT0-, 49 LVDS_GND49, 50 TX27/R6, 51 TX0/R0, 52 TX1/R1, 53 GND53, 54 TX2/R2, 55 TX3/R3, 56 TX4/R4

## NPN
designator Q?  value SS8050  (hidden comment: NPN)
TRAN NPN GEN 0.5A 45V AEC-Q101 SOT23; CAD_APPROVED: Yes; MFG_PN01: BC817,215; MFG_NAME01: NEXPERIA; AGILE_PN: 480-78842; Source_Path: Q:\ORCADCIS\SYMBOLS\FCL_SEMICONDUCTOR.OLB; CLASS: IC
footprint SOT23
pins: 1 BASE, 2 EMITTER, 3 COLLECTOR

## PIEZO_BUZZER_0
designator PZ?  value BUZZER  (hidden comment: PIEZO_BUZZER_0)
Source_Path: D:\NXP_RT1050\RT1050_MB_PRO\SCH\IMXRT1052_MB_PRO_0417_4.DSN
footprint BUZZER
pins: 1 +, 2 -

## POWER_JACK_3
designator JACK?  value POWER JACK_3  (hidden comment: POWER_JACK_3)
PCB DECAL: JACK-2_5MM_B; Source_Path: E:\WORK\SCH5\X\SCH\DEVELOP_BOARD_V1-5-21.DSN
footprint JACK-2_5MM_B
pins: 1 P, 2 G2, 3 G3

## R1005_0
designator R?  value 2.7K/1%  (hidden comment: R1005_0)
PCB DECAL: R0603; Source_Path: D:\SOPGODS_VIEW_AP\MOBILE_AP_APPLICATION\S3C6410\OUTPUT_DATA\HW\SMDK\INTEGRATION_BOARD\SMDK6410_CPU_BD_SCHEMATICS_REV0.0_EDITING.DSN
footprint R0603
pins: 1, 2

## RES
designator F?  value 0  (hidden comment: RES)
RES MF 1.0M 1/10W 5% 0402; AGILE_PN: 470-79978; MFG_NAME01: PANASONIC; MFG_PN01: ERJ-2GEJ105X; CAD_APPROVED: Yes; FPLIST: RC0402_25,RC0402_HD,0402_CC; PCB DECAL: F0805; Source_Path: Q:\ORCADCIS\SYMBOLS\FCL_RESISTOR.OLB; CLASS: DISCRETE
footprint F0805
pins: 1, 2

## RES_1
designator R?, comment value 1K  (hidden comment: RES)
RES MF 1.0M 1/10W 5% 0402; PCB DECAL: R0603; AGILE_PN: 470-79978; MFG_NAME01: PANASONIC; MFG_PN01: ERJ-2GEJ105X; CAD_APPROVED: Yes; FPLIST: RC0402_25,RC0402_HD,0402_CC; Source_Path: Q:\ORCADCIS\SYMBOLS\FCL_RESISTOR.OLB; CLASS: DISCRETE
footprint R0603
pins: 1, 2

## RES_2
designator R?, comment value 470  (hidden comment: RES)
RES MF 1.0M 1/10W 5% 0402; PCB DECAL: R0603; AGILE_PN: 470-79978; MFG_NAME01: PANASONIC; MFG_PN01: ERJ-2GEJ105X; CAD_APPROVED: Yes; FPLIST: RC0402_25,RC0402_HD,0402_CC; Source_Path: Q:\ORCADCIS\SYMBOLS\FCL_RESISTOR.OLB; CLASS: DISCRETE
footprint R0603
pins: 1, 2

## RES_3
designator R?, comment value 330  (hidden comment: RES)
RES MF 1.0M 1/10W 5% 0402; PCB DECAL: R0603; AGILE_PN: 470-79978; MFG_NAME01: PANASONIC; MFG_PN01: ERJ-2GEJ105X; CAD_APPROVED: Yes; FPLIST: RC0402_25,RC0402_HD,0402_CC; Source_Path: Q:\ORCADCIS\SYMBOLS\FCL_RESISTOR.OLB; CLASS: DISCRETE
footprint R0603
pins: 1, 2

## RES_4
designator R?  value 49.9R  Tolerance: 1%  PCB DECAL: R0603  (hidden comment: RES_4)
RES MF 4.7K 1/16W 5% 0402; AGILE_PN: 470-75626; MFG_NAME01: KOA SPEER; MFG_PN01: RK73B1ETTP472J; CAD_APPROVED: Yes; FPLIST: RC0402_25,RC0402_HD,0402_CC; CLASS: DISCRETE; Source_Path: F:\NXP\RT1020\SCH\IMXRT1021_0928.DSN
footprint R0603
pins: 1, 2

## RES_4_1
designator R?, comment value 100K  Tolerance: 1%  PCB DECAL: R0603  (hidden comment: RES_4)
RES MF 4.7K 1/16W 5% 0402; AGILE_PN: 470-75626; MFG_NAME01: KOA SPEER; MFG_PN01: RK73B1ETTP472J; CAD_APPROVED: Yes; FPLIST: RC0402_25,RC0402_HD,0402_CC; CLASS: DISCRETE; Source_Path: F:\NXP\RT1020\SCH\IMXRT1021_0928.DSN
footprint R0603
pins: 1, 2

## RES_4_2
designator R?, comment value 1K  PCB DECAL: R0603  (hidden comment: RES_4)
RES MF 4.7K 1/16W 5% 0402; AGILE_PN: 470-75626; MFG_NAME01: KOA SPEER; MFG_PN01: RK73B1ETTP472J; CAD_APPROVED: Yes; FPLIST: RC0402_25,RC0402_HD,0402_CC; CLASS: DISCRETE; Source_Path: F:\NXP\RT1020\SCH\IMXRT1021_0928.DSN
footprint R0603
pins: 1, 2

## RES_5
designator R?  value 3.4K  PCB DECAL: R0603  (hidden comment: RES_5)
RES MF 4.7K 1/16W 5% 0402; AGILE_PN: 470-75626; MFG_NAME01: KOA SPEER; MFG_PN01: RK73B1ETTP472J; CAD_APPROVED: Yes; FPLIST: RC0402_25,RC0402_HD,0402_CC; Source_Path: F:\NXP\RT1020\SCH\IMXRT1021_0928_1.DSN; CLASS: DISCRETE
footprint R0603
pins: 1, 2

## RES_5_1
designator R?, comment value 13.7K  Tolerance: 1%  PCB DECAL: R0603  (hidden comment: RES_5)
RES MF 4.7K 1/16W 5% 0402; AGILE_PN: 470-75626; MFG_NAME01: KOA SPEER; MFG_PN01: RK73B1ETTP472J; CAD_APPROVED: Yes; FPLIST: RC0402_25,RC0402_HD,0402_CC; Source_Path: F:\NXP\RT1020\SCH\IMXRT1021_0928_1.DSN; CLASS: DISCRETE
footprint R0603
pins: 1, 2

## RES_5_2
designator R?, comment value 200K  Tolerance: 1%  PCB DECAL: R0603  (hidden comment: RES_5)
RES MF 180K 1/10W 1% AEC-Q200 0402; Temp_Range: -55C to +155C; FPLIST: RC0402_25,RC0402_HD,0402_CC; CAD_APPROVED: Yes; MFG_PN01: RK73H1ETTP1803F; MFG_NAME01: KOA SPEER; AGILE_PN: 470-31088; Source_Path: F:\NXP\RT1020\SCH\IMXRT1021_0928_1.DSN; CLASS: DISCRETE
footprint R0603
pins: 1, 2

## RES_5_3
designator R?, comment value 10K  PCB DECAL: R0603  (hidden comment: RES_5)
RES MF 10K 1/16W 5% 0402; AGILE_PN: 470-75557; MFG_NAME01: VISHAY INTERTECHNOLOGY; MFG_PN01: CRCW040210K0JNED; CAD_APPROVED: Yes; FPLIST: RC0402_25,RC0402_HD,0402_CC; Source_Path: F:\NXP\RT1020\SCH\IMXRT1021_0928_1.DSN; CLASS: DISCRETE
footprint R0603
pins: 1, 2

## RES_5_4
designator R?, comment value 1K  PCB DECAL: R0603  (hidden comment: RES_5)
RES MF ZERO OHM 1/16W 5% 0402; FPLIST: RC0402_25,RC0402_HD,RC0402_X2,0402_CC; CAD_APPROVED: Yes; MFG_PN01: MCR01MZPJ000; MFG_NAME01: ROHM; AGILE_PN: 470-75394; Source_Path: F:\NXP\RT1020\SCH\IMXRT1021_0928_1.DSN; CLASS: DISCRETE
footprint R0603
pins: 1, 2

## RES_5_5
designator R?, comment value 44.2K  Tolerance: 1%  PCB DECAL: R0603  (hidden comment: RES_5)
RES MF 180K 1/10W 1% AEC-Q200 0402; Temp_Range: -55C to +155C; FPLIST: RC0402_25,RC0402_HD,0402_CC; CAD_APPROVED: Yes; MFG_PN01: RK73H1ETTP1803F; MFG_NAME01: KOA SPEER; AGILE_PN: 470-31088; Source_Path: F:\NXP\RT1020\SCH\IMXRT1021_0928_1.DSN; CLASS: DISCRETE
footprint R0603
pins: 1, 2

## RES_5_6
designator R?, comment value 10K  PCB DECAL: R0603  (hidden comment: RES_5)
RES MF 4.7K 1/16W 5% 0402; AGILE_PN: 470-75626; MFG_NAME01: KOA SPEER; MFG_PN01: RK73B1ETTP472J; CAD_APPROVED: Yes; FPLIST: RC0402_25,RC0402_HD,0402_CC; Source_Path: F:\NXP\RT1020\SCH\IMXRT1021_0928_1.DSN; CLASS: DISCRETE
footprint R0603
pins: 1, 2

## RES_5_7
designator R?, comment value 4.7K  PCB DECAL: R0603  (hidden comment: RES_5)
RES MF 4.7K 1/16W 5% 0402; AGILE_PN: 470-75626; MFG_NAME01: KOA SPEER; MFG_PN01: RK73B1ETTP472J; CAD_APPROVED: Yes; FPLIST: RC0402_25,RC0402_HD,0402_CC; Source_Path: F:\NXP\RT1020\SCH\IMXRT1021_0928_1.DSN; CLASS: DISCRETE
footprint R0603
pins: 1, 2

## RES_5_8
designator R?, comment value 1K  PCB DECAL: R0603  (hidden comment: RES_5)
RES MF 4.7K 1/16W 5% 0402; FPLIST: RC0402_25,RC0402_HD,0402_CC; CAD_APPROVED: Yes; MFG_PN01: RK73B1ETTP472J; MFG_NAME01: KOA SPEER; AGILE_PN: 470-75626; Source_Path: F:\NXP\RT1020\SCH\IMXRT1021_0928_1.DSN; CLASS: DISCRETE
footprint R0603
pins: 1, 2

## RES_5_9
designator R?, comment value 20R  PCB DECAL: R0603  (hidden comment: RES_5)
RES MF 4.7K 1/16W 5% 0402; AGILE_PN: 470-75626; MFG_NAME01: KOA SPEER; MFG_PN01: RK73B1ETTP472J; CAD_APPROVED: Yes; FPLIST: RC0402_25,RC0402_HD,0402_CC; Source_Path: F:\NXP\RT1020\SCH\IMXRT1021_0928_1.DSN; CLASS: DISCRETE
footprint R0603
pins: 1, 2

## RES_5_10
designator R?, comment value 120R  PCB DECAL: R0603  (hidden comment: RES_5)
RES MF 4.7K 1/16W 5% 0402; AGILE_PN: 470-75626; MFG_NAME01: KOA SPEER; MFG_PN01: RK73B1ETTP472J; CAD_APPROVED: Yes; FPLIST: RC0402_25,RC0402_HD,0402_CC; Source_Path: F:\NXP\RT1020\SCH\IMXRT1021_0928_1.DSN; CLASS: DISCRETE
footprint R0603
pins: 1, 2

## RES_5_11
designator R?, comment value 5.1K  PCB DECAL: R0603  (hidden comment: RES_5)
RES MF 4.7K 1/16W 5% 0402; FPLIST: RC0402_25,RC0402_HD,0402_CC; CAD_APPROVED: Yes; MFG_PN01: RK73B1ETTP472J; MFG_NAME01: KOA SPEER; AGILE_PN: 470-75626; Source_Path: F:\NXP\RT1020\SCH\IMXRT1021_0928_1.DSN; CLASS: DISCRETE
footprint R0603
pins: 1, 2

## RES_5_12
designator R?, comment value 0R  PCB DECAL: R0603  (hidden comment: RES_5)
RES MF 4.7K 1/16W 5% 0402; AGILE_PN: 470-75626; MFG_NAME01: KOA SPEER; MFG_PN01: RK73B1ETTP472J; CAD_APPROVED: Yes; FPLIST: RC0402_25,RC0402_HD,0402_CC; Source_Path: F:\NXP\RT1020\SCH\IMXRT1021_0928_1.DSN; CLASS: DISCRETE
footprint R0603
pins: 1, 2

## RES_5_13
designator R?, comment value NC  PCB DECAL: R0603  (hidden comment: RES_5)
RES MF 4.7K 1/16W 5% 0402; FPLIST: RC0402_25,RC0402_HD,0402_CC; CAD_APPROVED: Yes; MFG_PN01: RK73B1ETTP472J; MFG_NAME01: KOA SPEER; AGILE_PN: 470-75626; Source_Path: F:\NXP\RT1020\SCH\IMXRT1021_0928_1.DSN; CLASS: DISCRETE
footprint R0603
pins: 1, 2

## RES_5_14
designator R?, comment value 100R  PCB DECAL: R0603  (hidden comment: RES_5)
RES MF 4.7K 1/16W 5% 0402; FPLIST: RC0402_25,RC0402_HD,0402_CC; CAD_APPROVED: Yes; MFG_PN01: RK73B1ETTP472J; MFG_NAME01: KOA SPEER; AGILE_PN: 470-75626; Source_Path: F:\NXP\RT1020\SCH\IMXRT1021_0928_1.DSN; CLASS: DISCRETE
footprint R0603
pins: 1, 2

## RES_5_15
designator R?, comment value 220R  PCB DECAL: R0603  (hidden comment: RES_5)
RES MF 4.7K 1/16W 5% 0402; FPLIST: RC0402_25,RC0402_HD,0402_CC; CAD_APPROVED: Yes; MFG_PN01: RK73B1ETTP472J; MFG_NAME01: KOA SPEER; AGILE_PN: 470-75626; Source_Path: F:\NXP\RT1020\SCH\IMXRT1021_0928_1.DSN; CLASS: DISCRETE
footprint R0603
pins: 1, 2

## RES_5_16
designator R?, comment value 6.49K  PCB DECAL: R0603  (hidden comment: RES_5)
RES MF 4.7K 1/16W 5% 0402; AGILE_PN: 470-75626; MFG_NAME01: KOA SPEER; MFG_PN01: RK73B1ETTP472J; CAD_APPROVED: Yes; FPLIST: RC0402_25,RC0402_HD,0402_CC; Source_Path: F:\NXP\RT1020\SCH\IMXRT1021_0928_1.DSN; CLASS: DISCRETE
footprint R0603
pins: 1, 2

## RES_5_17
designator R?, comment value 2.2K  PCB DECAL: R0603  (hidden comment: RES_5)
RES MF 4.7K 1/16W 5% 0402; AGILE_PN: 470-75626; MFG_NAME01: KOA SPEER; MFG_PN01: RK73B1ETTP472J; CAD_APPROVED: Yes; FPLIST: RC0402_25,RC0402_HD,0402_CC; Source_Path: F:\NXP\RT1020\SCH\IMXRT1021_0928_1.DSN; CLASS: DISCRETE
footprint R0603
pins: 1, 2

## RES_5_18
designator R?, comment value 6.8K  PCB DECAL: R0603  (hidden comment: RES_5)
RES MF 4.7K 1/16W 5% 0402; AGILE_PN: 470-75626; MFG_NAME01: KOA SPEER; MFG_PN01: RK73B1ETTP472J; CAD_APPROVED: Yes; FPLIST: RC0402_25,RC0402_HD,0402_CC; Source_Path: F:\NXP\RT1020\SCH\IMXRT1021_0928_1.DSN; CLASS: DISCRETE
footprint R0603
pins: 1, 2

## RES_5_19
designator R?, comment value 100K  PCB DECAL: R0603  (hidden comment: RES_5)
RES MF 4.7K 1/16W 5% 0402; AGILE_PN: 470-75626; MFG_NAME01: KOA SPEER; MFG_PN01: RK73B1ETTP472J; CAD_APPROVED: Yes; FPLIST: RC0402_25,RC0402_HD,0402_CC; Source_Path: F:\NXP\RT1020\SCH\IMXRT1021_0928_1.DSN; CLASS: DISCRETE
footprint R0603
pins: 1, 2

## RES_5_20
designator R?, comment value 47K  PCB DECAL: R0603  (hidden comment: RES_5)
RES MF 4.7K 1/16W 5% 0402; AGILE_PN: 470-75626; MFG_NAME01: KOA SPEER; MFG_PN01: RK73B1ETTP472J; CAD_APPROVED: Yes; FPLIST: RC0402_25,RC0402_HD,0402_CC; Source_Path: F:\NXP\RT1020\SCH\IMXRT1021_0928_1.DSN; CLASS: DISCRETE
footprint R0603
pins: 1, 2

## RES_5_21
designator R?, comment value NC/10K  PCB DECAL: R0603  (hidden comment: RES_5)
RES MF 4.7K 1/16W 5% 0402; FPLIST: RC0402_25,RC0402_HD,0402_CC; CAD_APPROVED: Yes; MFG_PN01: RK73B1ETTP472J; MFG_NAME01: KOA SPEER; AGILE_PN: 470-75626; Source_Path: F:\NXP\RT1020\SCH\IMXRT1021_0928_1.DSN; CLASS: DISCRETE
footprint R0603
pins: 1, 2

## RES_5_22
designator R?, comment value 4.3K  PCB DECAL: R0603  (hidden comment: RES_5)
RES MF 4.7K 1/16W 5% 0402; AGILE_PN: 470-75626; MFG_NAME01: KOA SPEER; MFG_PN01: RK73B1ETTP472J; CAD_APPROVED: Yes; FPLIST: RC0402_25,RC0402_HD,0402_CC; Source_Path: F:\NXP\RT1020\SCH\IMXRT1021_0928_1.DSN; CLASS: DISCRETE
footprint R0603
pins: 1, 2

## RES_5_23
designator R?, comment value 470R  PCB DECAL: R0603  (hidden comment: RES_5)
RES MF 4.7K 1/16W 5% 0402; FPLIST: RC0402_25,RC0402_HD,0402_CC; CAD_APPROVED: Yes; MFG_PN01: RK73B1ETTP472J; MFG_NAME01: KOA SPEER; AGILE_PN: 470-75626; Source_Path: F:\NXP\RT1020\SCH\IMXRT1021_0928_1.DSN; CLASS: DISCRETE
footprint R0603
pins: 1, 2

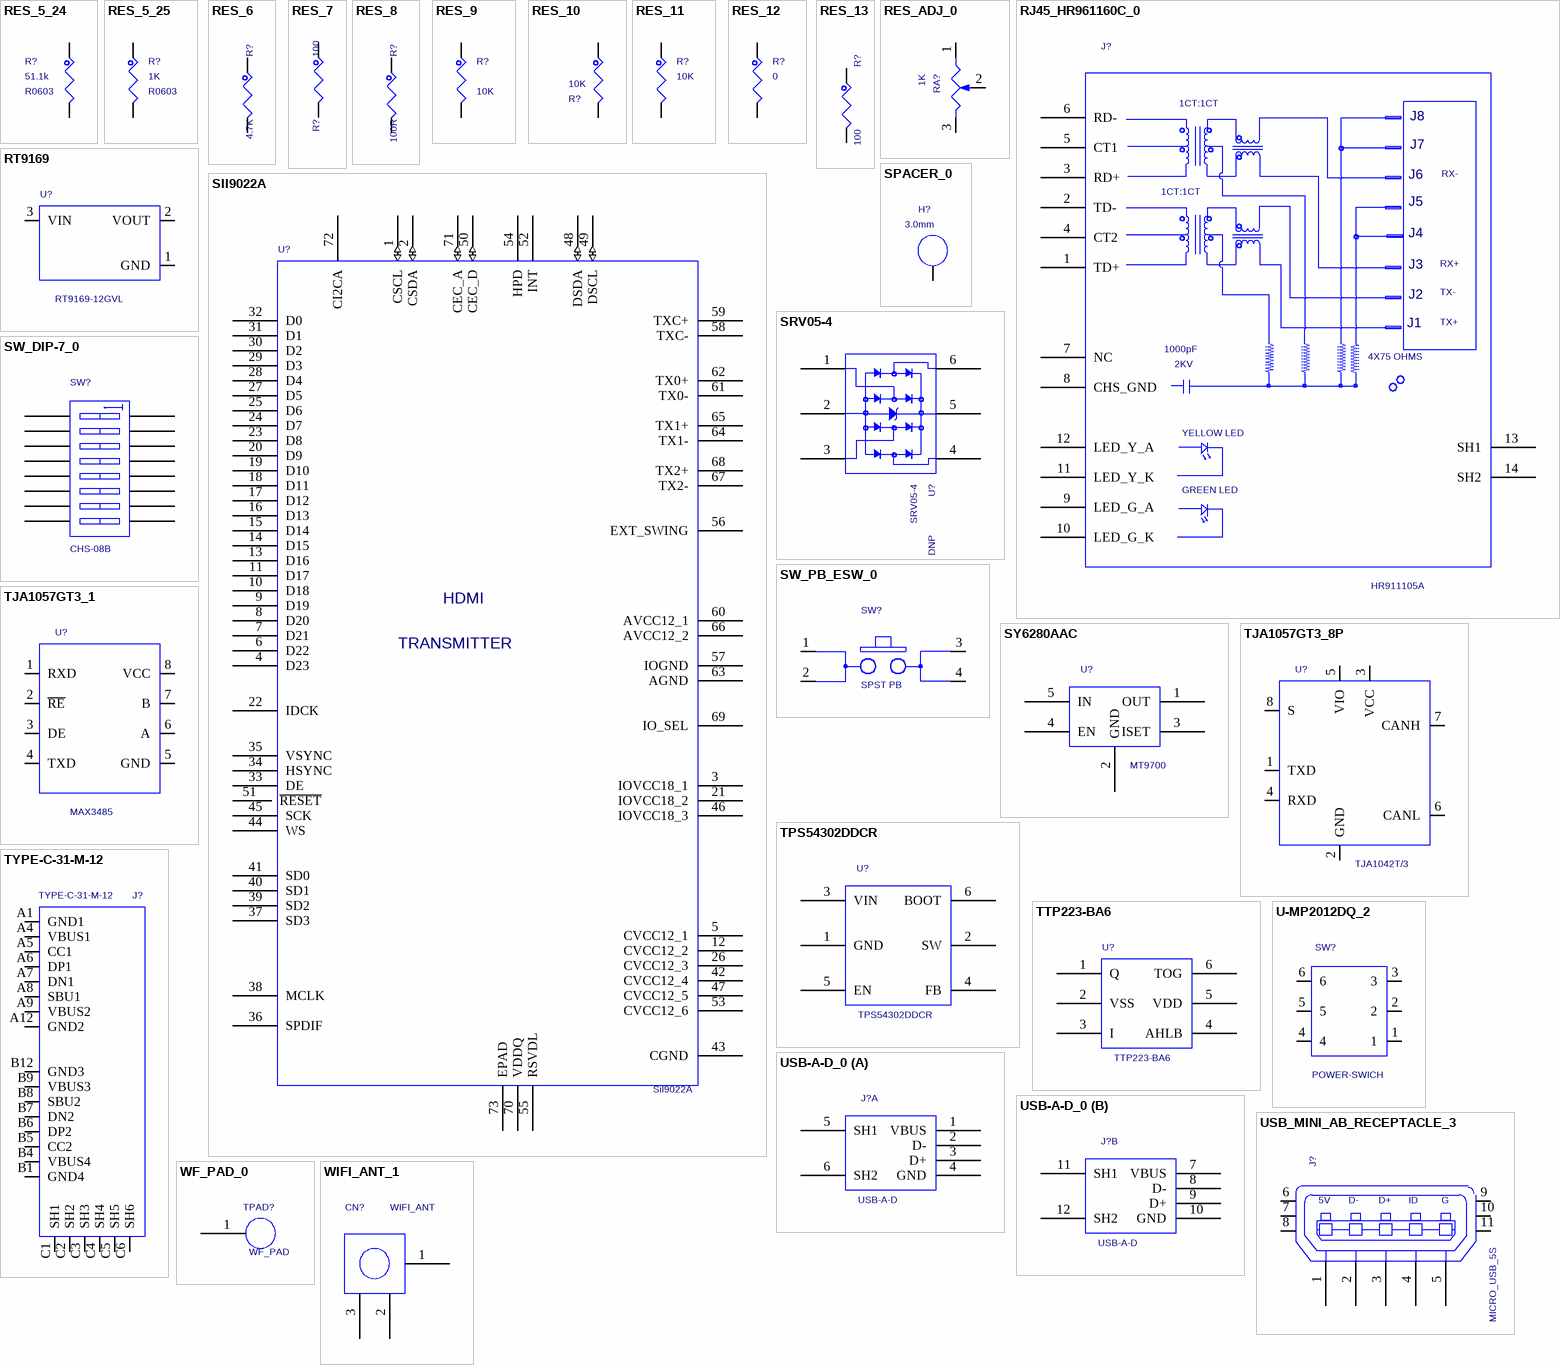
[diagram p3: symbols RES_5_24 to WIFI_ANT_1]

## RES_5_24
designator R?, comment value 51.1k  PCB DECAL: R0603  (hidden comment: RES_5)
RES MF 4.7K 1/16W 5% 0402; FPLIST: RC0402_25,RC0402_HD,0402_CC; CAD_APPROVED: Yes; MFG_PN01: RK73B1ETTP472J; MFG_NAME01: KOA SPEER; AGILE_PN: 470-75626; Source_Path: F:\NXP\RT1020\SCH\IMXRT1021_0928_1.DSN; CLASS: DISCRETE
footprint R0603
pins: 1, 2

## RES_5_25
designator R?, comment value 1K  PCB DECAL: R0603  (hidden comment: RES_5)
RES MF 10K 1/16W 5% 0402; AGILE_PN: 470-75557; MFG_NAME01: VISHAY INTERTECHNOLOGY; MFG_PN01: CRCW040210K0JNED; CAD_APPROVED: Yes; FPLIST: RC0402_25,RC0402_HD,0402_CC; Source_Path: F:\NXP\RT1020\SCH\IMXRT1021_0928_1.DSN; CLASS: DISCRETE
footprint R0603
pins: 1, 2

## RES_6
designator R?, comment value 4.7K  (hidden comment: RES)
RES MF 1.0M 1/10W 5% 0402; PCB DECAL: R0603; FPLIST: RC0402_25,RC0402_HD,0402_CC; CAD_APPROVED: Yes; MFG_PN01: ERJ-2GEJ105X; MFG_NAME01: PANASONIC; AGILE_PN: 470-79978; Source_Path: Q:\ORCADCIS\SYMBOLS\FCL_RESISTOR.OLB; CLASS: DISCRETE
footprint R0603
pins: 1, 2

## RES_7
designator R?, comment value 100  (hidden comment: RES)
RES MF 1.0M 1/10W 5% 0402; PCB DECAL: R0603; AGILE_PN: 470-79978; MFG_NAME01: PANASONIC; MFG_PN01: ERJ-2GEJ105X; CAD_APPROVED: Yes; FPLIST: RC0402_25,RC0402_HD,0402_CC; Source_Path: Q:\ORCADCIS\SYMBOLS\FCL_RESISTOR.OLB; CLASS: DISCRETE
footprint R0603
pins: 1, 2

## RES_8
designator R?, comment value 100R  (hidden comment: RES)
RES MF 1.0M 1/10W 5% 0402; PCB DECAL: R0603; FPLIST: RC0402_25,RC0402_HD,0402_CC; CAD_APPROVED: Yes; MFG_PN01: ERJ-2GEJ105X; MFG_NAME01: PANASONIC; AGILE_PN: 470-79978; Source_Path: Q:\ORCADCIS\SYMBOLS\FCL_RESISTOR.OLB; CLASS: DISCRETE
footprint R0603
pins: 1, 2

## RES_9
designator R?, comment value 10K  (hidden comment: RES)
RES MF 10.0K 1/16W 1% AEC-Q200 0402; PCB DECAL: R0603; SIGNAL_MODEL: DEFAULT_RESISTOR_10000OHM_2_1; AGILE_PN: 470-75416; MFG_NAME01: KOA SPEER; MFG_PN01: RK73H1ETTP1002F; CAD_APPROVED: Yes; FPLIST: RC0402_25,RC0402_HD,0402_CC; CLASS: DISCRETE; Source_Path: Q:\ORCADCIS\SYMBOLS\FCL_RESISTOR.OLB
footprint R0603
pins: 1, 2

## RES_10
designator R?, comment value 10K  (hidden comment: RES)
RES MF 1.0M 1/10W 5% 0402; AGILE_PN: 470-79978; MFG_NAME01: PANASONIC; MFG_PN01: ERJ-2GEJ105X; CAD_APPROVED: Yes; FPLIST: RC0402_25,RC0402_HD,0402_CC; PCB DECAL: R0603; Source_Path: Q:\ORCADCIS\SYMBOLS\FCL_RESISTOR.OLB; CLASS: DISCRETE
footprint R0603
pins: 1, 2

## RES_11
designator R?, comment value 10K  (hidden comment: RES)
RES MF 10K 1/16W 5% 0402; AGILE_PN: 470-75557; MFG_NAME01: VISHAY INTERTECHNOLOGY; MFG_PN01: CRCW040210K0JNED; CAD_APPROVED: Yes; FPLIST: RC0402_25,RC0402_HD,0402_CC; PCB DECAL: R0603; Source_Path: Q:\ORCADCIS\SYMBOLS\FCL_RESISTOR.OLB; CLASS: DISCRETE
footprint R0603
pins: 1, 2

## RES_12
designator R?, comment value 0  (hidden comment: RES)
RES MF ZERO OHM 1/8W -- 0805; PCB DECAL: R0805; AGILE_PN: 470-75442; Tolerance: 5%; MFG_NAME01: YAGEO AMERICA; MFG_PN01: RC0805JR-070RL; CAD_APPROVED: Yes; FPLIST: RC0805_OV,RC0805,RC0805_OV_3P,0805_CC; Source_Path: Q:\ORCADCIS\SYMBOLS\FCL_RESISTOR.OLB; CLASS: DISCRETE
footprint R0805
pins: 1, 2

## RES_13
designator R?, comment value 100  (hidden comment: RES)
RES MF 100 OHM 1/16W 1% 0402; PCB DECAL: R0603; AGILE_PN: 470-30454; MFG_NAME01: THYE MING TECH CO LTD; MFG_PN01: CR-02FL6--100R; CAD_APPROVED: Yes; FPLIST: RC0402_25,RC0402_HD,0402_CC; Source_Path: Q:\ORCADCIS\SYMBOLS\FCL_RESISTOR.OLB; CLASS: DISCRETE
footprint R0603
pins: 1, 2

## RES_ADJ_0
designator RA?  value 1K  (hidden comment: RES_ADJ_0)
Single Turn Top Adjust, 3362P; Part_Number: RE700010-01; Mfr_Part_Number: 3362P-1-203LF; Mfr: Bourns; Partname: DIP可调电阻 3362; Power: 1/2W; Gtech_Number: 50700011202KR0201; Remarks: Checked; Spec: 20K,3362P-1-203LF(Bourns); PCB DECAL: RM065-V1; Source_Path: D:\NXP_RT1050\PCB\IMXRT1052-180207\SCH\RT1050_MB_PRO\IMXRT1052_MB_PRO_0502.DSN
footprint RM065-V1
pins: 1, 2, 3

## RJ45_HR961160C_0
designator J?  value HR911105A  (hidden comment: RJ45_HR961160C_0)
CON 12 RJ45 SHLD RA SM 1.02MM SP 625H --; AGILE_PN: 211-79967; MFG_NAME01: HanRun Electronics Co., Ltd; CAD_APPROVED: Yes; Source_Path: H:\NXP_RT1050\SCH\IMXRT1052_MB.DSN; CLASS: IO
footprint RJ45
pins: 1 TD+, 2 TD-, 3 RD+, 4 CT2, 5 CT1, 6 RD-, 7 NC, 8 CHS_GND, 9 LED_G_A, 10 LED_G_K, 11 LED_Y_K, 12 LED_Y_A, 13 SH1, 14 SH2

## RT9169
designator U?  value RT9169-12GVL  (hidden comment: RT9169)
PCB DECAL: SOT23; Source_Path: F:\NXP\I.MX6UL\SCH\IMX6UL.OLB; CLASS: IC
footprint SOT23
pins: 1 GND (power), 2 VOUT, 3 VIN

## SII9022A
designator U?
IC XMTR HDMI 165MHZ 1.8/3.3V QFN72; AGILE_PN: 312-79886; MFG_NAME01: SILICON IMAGE; MFG_PN01: SiI9022ACNU; ASSY_OPT: DNP; CAD_APPROVED: Yes; PCB DECAL: QFN72_0P5_10X10_4P85SQ; Source_Path: Q:\ORCADCIS\SYMBOLS\FCL_IC4.OLB
footprint QFN72_0P5_10X10_4P85SQ
pins: 1 CSCL (io), 2 CSDA (io), 3 IOVCC18_1 (power), 4 D23, 5 CVCC12_1 (power), 6 D22, 7 D21, 8 D20, 9 D19, 10 D18, 11 D17, 12 CVCC12_2 (power), 13 D16, 14 D15, 15 D14, 16 D13, 17 D12, 18 D11, 19 D10, 20 D9, 21 IOVCC18_2 (power), 22 IDCK, 23 D8, 24 D7, 25 D6, 26 CVCC12_3 (power), 27 D5, 28 D4, 29 D3, 30 D2, 31 D1, 32 D0, 33 DE, 34 HSYNC, 35 VSYNC, 36 SPDIF, 37 SD3, 38 MCLK, 39 SD2, 40 SD1, 41 SD0, 42 CVCC12_4 (power), 43 CGND (power), 44 WS, 45 SCK, 46 IOVCC18_3 (power), 47 CVCC12_5 (power), 48 DSDA (io), 49 DSCL (io), 50 CEC_D (io), 51 ~{RESET}, 52 INT, 53 CVCC12_6 (power), 54 HPD, 55 RSVDL, 56 EXT_SWING, 57 IOGND (power), 58 TXC-, 59 TXC+, 60 AVCC12_1 (power), 61 TX0-, 62 TX0+, 63 AGND (power), 64 TX1-, 65 TX1+, 66 AVCC12_2 (power), 67 TX2-, 68 TX2+, 69 IO_SEL, 70 VDDQ (power), 71 CEC_A (io), 72 CI2CA, 73 EPAD (power)

## SPACER_0
designator H?  value 3.0mm  (hidden comment: SPACER_0)
FASTENER, STANDOFF 4.5MMX3.53XM3.0X0.5 ROUND THR .635"L BRASS; PCB DECAL: T4R2-6R2_BOTSMT; AGILE_PN: 280-76498; MFG_NAME01: UNICORP; MFG_PN01: MSS251-R-1-A-16; ASSY_OPT: DNP; CAD_APPROVED: Yes; Source_Path: H:\NXP_RT1050\SCH\IMXRT1052.DSN; CLASS: IC
footprint T4R2-6R2_BOTSMT
pins: 1 NC_1

## SRV05-4
designator U?  ASSY_OPT: DNP  (hidden comment: SRV05-4)
DIODE TVS ARRAY 12A 5V 300W SOT23_S6; CAD_APPROVED: Yes; MFG_PN01: SRV05-4.TCT; MFG_NAME01: SEMTECH CORP; AGILE_PN: 480-75205; Source_Path: Q:\ORCADCIS\SYMBOLS\FCL_SEMICONDUCTOR.OLB; CLASS: IC
footprint SOT23_S6
pins: 1 I/O1, 2 GND, 3 I/O3, 4 I/O4, 5 VCC, 6 I/O6

## SW_DIP-7_0
designator SW?  value CHS-08B  (hidden comment: SW_DIP-7_0)
Source_Path: F:\SCH-PCB\EBF_L002\SCH\EBF_L002.DSN
footprint CHS-08B
pins: 1 A1, 2 A2, 3 A3, 4 A4, 5 A5, 6 A6, 7 A7, 8 A8, 9 B8, 10 B7, 11 B6, 12 B5, 13 B4, 14 B3, 15 B2, 16 B1

## SW_PB_ESW_0
designator SW?  value SPST PB  (hidden comment: SW_PB_ESW_0)
SW SPST MOM NO PB TACT 50mA 50V SMT; PCB DECAL: SW4_PB_ESW_SM_P177; CAD_APPROVED: Yes; MFG_PN01: TL3301AF260QG/TR; MFG_NAME01: E SWITCH; AGILE_PN: 510-77562; Source_Path: H:\NXP_RT1050\SCH\IMXRT1052_MB.DSN; CLASS: IC
footprint SW4_PB_ESW_SM_P177
pins: 1 A1, 2 A2, 3 B1, 4 B2

## SY6280AAC
designator U?  value MT9700  (hidden comment: SY6280AAC)
PCB DECAL: SOT23-5; Source_Path: G:\开发板代码\郭老师资料\IMX6资料\原理图\SABRESDB_DESIGNFILES\DEVELOP\LIBRARY1.OLB
footprint SOT23-5
pins: 1 OUT, 2 GND, 3 ISET, 4 EN, 5 IN

## TJA1057GT3_1
designator U?  value MAX3485  (hidden comment: TJA1057GT3_1)
IC XCVR CAN 4.75-5.25V/2.95-5.25V AEC-Q100 SO8; PCB DECAL: SOP8; AGILE_PN: 312-81479; MFG_NAME01: NXP SEMICONDUCTORS; MFG_PN01: TJA1057GT/3; CAD_APPROVED: Yes; Source_Path: H:\NXP_RT1050\SCH\IMXRT1052_MB.DSN
footprint SOP8
pins: 1 RXD, 2 ~{RE}, 3 DE, 4 TXD, 5 GND, 6 A, 7 B, 8 VCC

## TJA1057GT3_8P
designator U?  value TJA1042T/3  (hidden comment: TJA1057GT3_8P)
IC XCVR CAN 4.75-5.25V/2.95-5.25V AEC-Q100 SO8; PCB DECAL: SOP8; CAD_APPROVED: Yes; MFG_PN01: TJA1057GT/3; MFG_NAME01: NXP SEMICONDUCTORS; AGILE_PN: 312-81479; Source_Path: Q:\ORCADCIS\SYMBOLS\FCL_IC5.OLB
footprint SOP8
pins: 1 TXD, 2 GND (power), 3 VCC (power), 4 RXD, 5 VIO (power), 6 CANL (io), 7 CANH (io), 8 S

## TPS54302DDCR
designator U?
PCB DECAL: SOT23_S6; Source_Path: E:\20200512_SH_HONGDING_CUSTOMIZED\SCH\LIBRARY1.OLB
footprint SOT23_S6
pins: 1 GND, 2 SW, 3 VIN, 4 FB, 5 EN, 6 BOOT

## TTP223-BA6
designator U?
PCB DECAL: SOT23-6; Source_Path: F:\SCH-PCB\FPGA\EBF_F002\SCH\EBF_F002.OLB
footprint SOT23-6
pins: 1 Q, 2 VSS, 3 I, 4 AHLB, 5 VDD, 6 TOG

## TYPE-C-31-M-12
designator J?
Source_Path: C:\MYPROGRAM\CADENCE\SPB_16.6\TOOLS\CAPTURE\LIBRARY\SCH.OLB
footprint TYPE-C-31-M-12
pins: A1 GND1, A4 VBUS1, A5 CC1, A6 DP1, A7 DN1, A8 SBU1, A9 VBUS2, A12 GND2, B1 GND4, B4 VBUS4, B5 CC2, B6 DP2, B7 DN2, B8 SBU2, B9 VBUS3, B12 GND3, C1 SH1, C2 SH2, C3 SH3, C4 SH4, C5 SH5, C6 SH6

## U-MP2012DQ_2
designator SW?  value POWER-SWICH  (hidden comment: U-MP2012DQ_2)
PCB DECAL: SWITCH_DDSZ; Source_Path: H:\NXP_RT1050\SCH\IMXRT1052_MB.DSN
footprint SWITCH_DDSZ
pins: 1, 2, 3, 4, 5, 6

## USB-A-D_0
designator J?  value USB-A-D  (hidden comment: USB-A-D_0)
Source_Path: D:\NXP_RT1050\RT1050_MB_PRO\SCH\IMXRT1052_MB_PRO_0313.DSN
footprint USB-A-D
part A pins: 1 VBUS, 2 D-, 3 D+, 4 GND, 5 SH1, 6 SH2
part B pins: 7 VBUS, 8 D-, 9 D+, 10 GND, 11 SH1, 12 SH2

## USB_MINI_AB_RECEPTACLE_3
designator J?  value MICRO_USB_5S  (hidden comment: USB_MINI_AB_RECEPTACLE_3)
CON 5 USB MICRO_AB RA SKT SMT 0.65MM SP 110H AU; AGILE_PN: 211-80104; MFG_NAME01: ANYTRONIC CORPORATION LIMITED; MFG_PN01: 23970101#LCP-58LF; Temp_Range: -55&#8451; to 105&#8451;; CAD_APPROVED: Yes; Source_Path: D:\NXP_RT1050\RT1050_MB_PRO\SCH\IMXRT1052_MB_PRO_0418.DSN; CLASS: IO
footprint MICRO_USB_5S
pins: 1 P1, 2 P2, 3 P3, 4 P4, 5 P5, 6 SHLD1, 7 SHLD2, 8 SHLD3, 9 SHLD4, 10 SHLD5, 11 SHLD6

## WF_PAD_0
designator TPAD?  value WF_PAD  (hidden comment: WF_PAD_0)
Source_Path: H:\NXP_RT1050\SCH\IMXRT1052_MB.DSN
footprint WF_PAD
pins: 1

## WIFI_ANT_1
designator CN?  value WIFI_ANT  (hidden comment: WIFI_ANT_1)
PCB DECAL: UFL-3; Source_Path: H:\NXP_RT1050\SCH\IMXRT1052_MB.DSN
footprint UFL-3
pins: 1, 2, 3

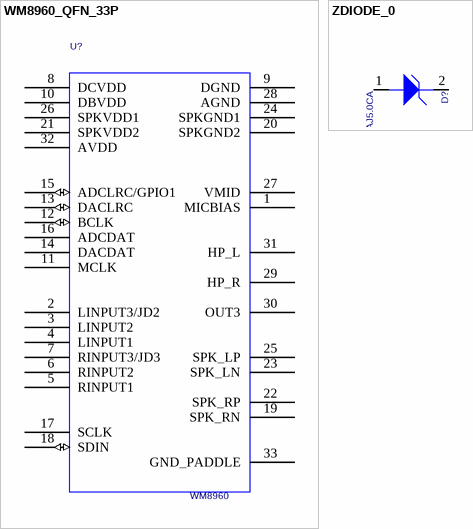
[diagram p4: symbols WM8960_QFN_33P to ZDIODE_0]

## WM8960_QFN_33P
designator U?  value WM8960  (hidden comment: WM8960_QFN_33P)
IC CODEC STEREO WITH CLASS D SPEAKER DRIVER 1.71-3.6V QFN32; AGILE_PN: 315-79450; MFG_NAME01: WOLFSON MICROELECTRONICS; MFG_PN01: WM8960CGEFL/RV; CAD_APPROVED: Yes; Source_Path: Q:\ORCADCIS\SYMBOLS\FCL_IC2.OLB
footprint QFN32
pins: 1 MICBIAS, 2 LINPUT3/JD2, 3 LINPUT2, 4 LINPUT1, 5 RINPUT1, 6 RINPUT2, 7 RINPUT3/JD3, 8 DCVDD (power), 9 DGND (power), 10 DBVDD (power), 11 MCLK, 12 BCLK (io), 13 DACLRC (io), 14 DACDAT, 15 ADCLRC/GPIO1 (io), 16 ADCDAT, 17 SCLK, 18 SDIN (io), 19 SPK_RN, 20 SPKGND2 (power), 21 SPKVDD2 (power), 22 SPK_RP, 23 SPK_LN, 24 SPKGND1 (power), 25 SPK_LP, 26 SPKVDD1 (power), 27 VMID, 28 AGND (power), 29 HP_R, 30 OUT3, 31 HP_L, 32 AVDD (power), 33 GND_PADDLE (power)

## ZDIODE_0
designator D?  value SMAJ5.0CA  (hidden comment: ZDIODE_0)
DIODE ZNR -- 0.2W 5.1V AEC-Q101 SOD523; AGILE_PN: 480-77217; MFG_NAME01: ON SEMICONDUCTOR; MFG_PN01: MM5Z5V1ST1G; CAD_APPROVED: Yes; PCB DECAL: DO214; Source_Path: H:\NXP_RT1050\SCH\IMXRT1052_MB.DSN; CLASS: IC
footprint DO214
pins: 1 ANODE, 2 CATHODE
